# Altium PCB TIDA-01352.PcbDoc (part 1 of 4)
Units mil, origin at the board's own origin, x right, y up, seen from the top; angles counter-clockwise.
Board outline 6496.06 x 8661.42 mil, 4 copper layers (Top Layer, GND, PWR, Bottom Layer), stack 79.834 mil thick; 456 components, 240 nets, 1197 pads, 446 vias.
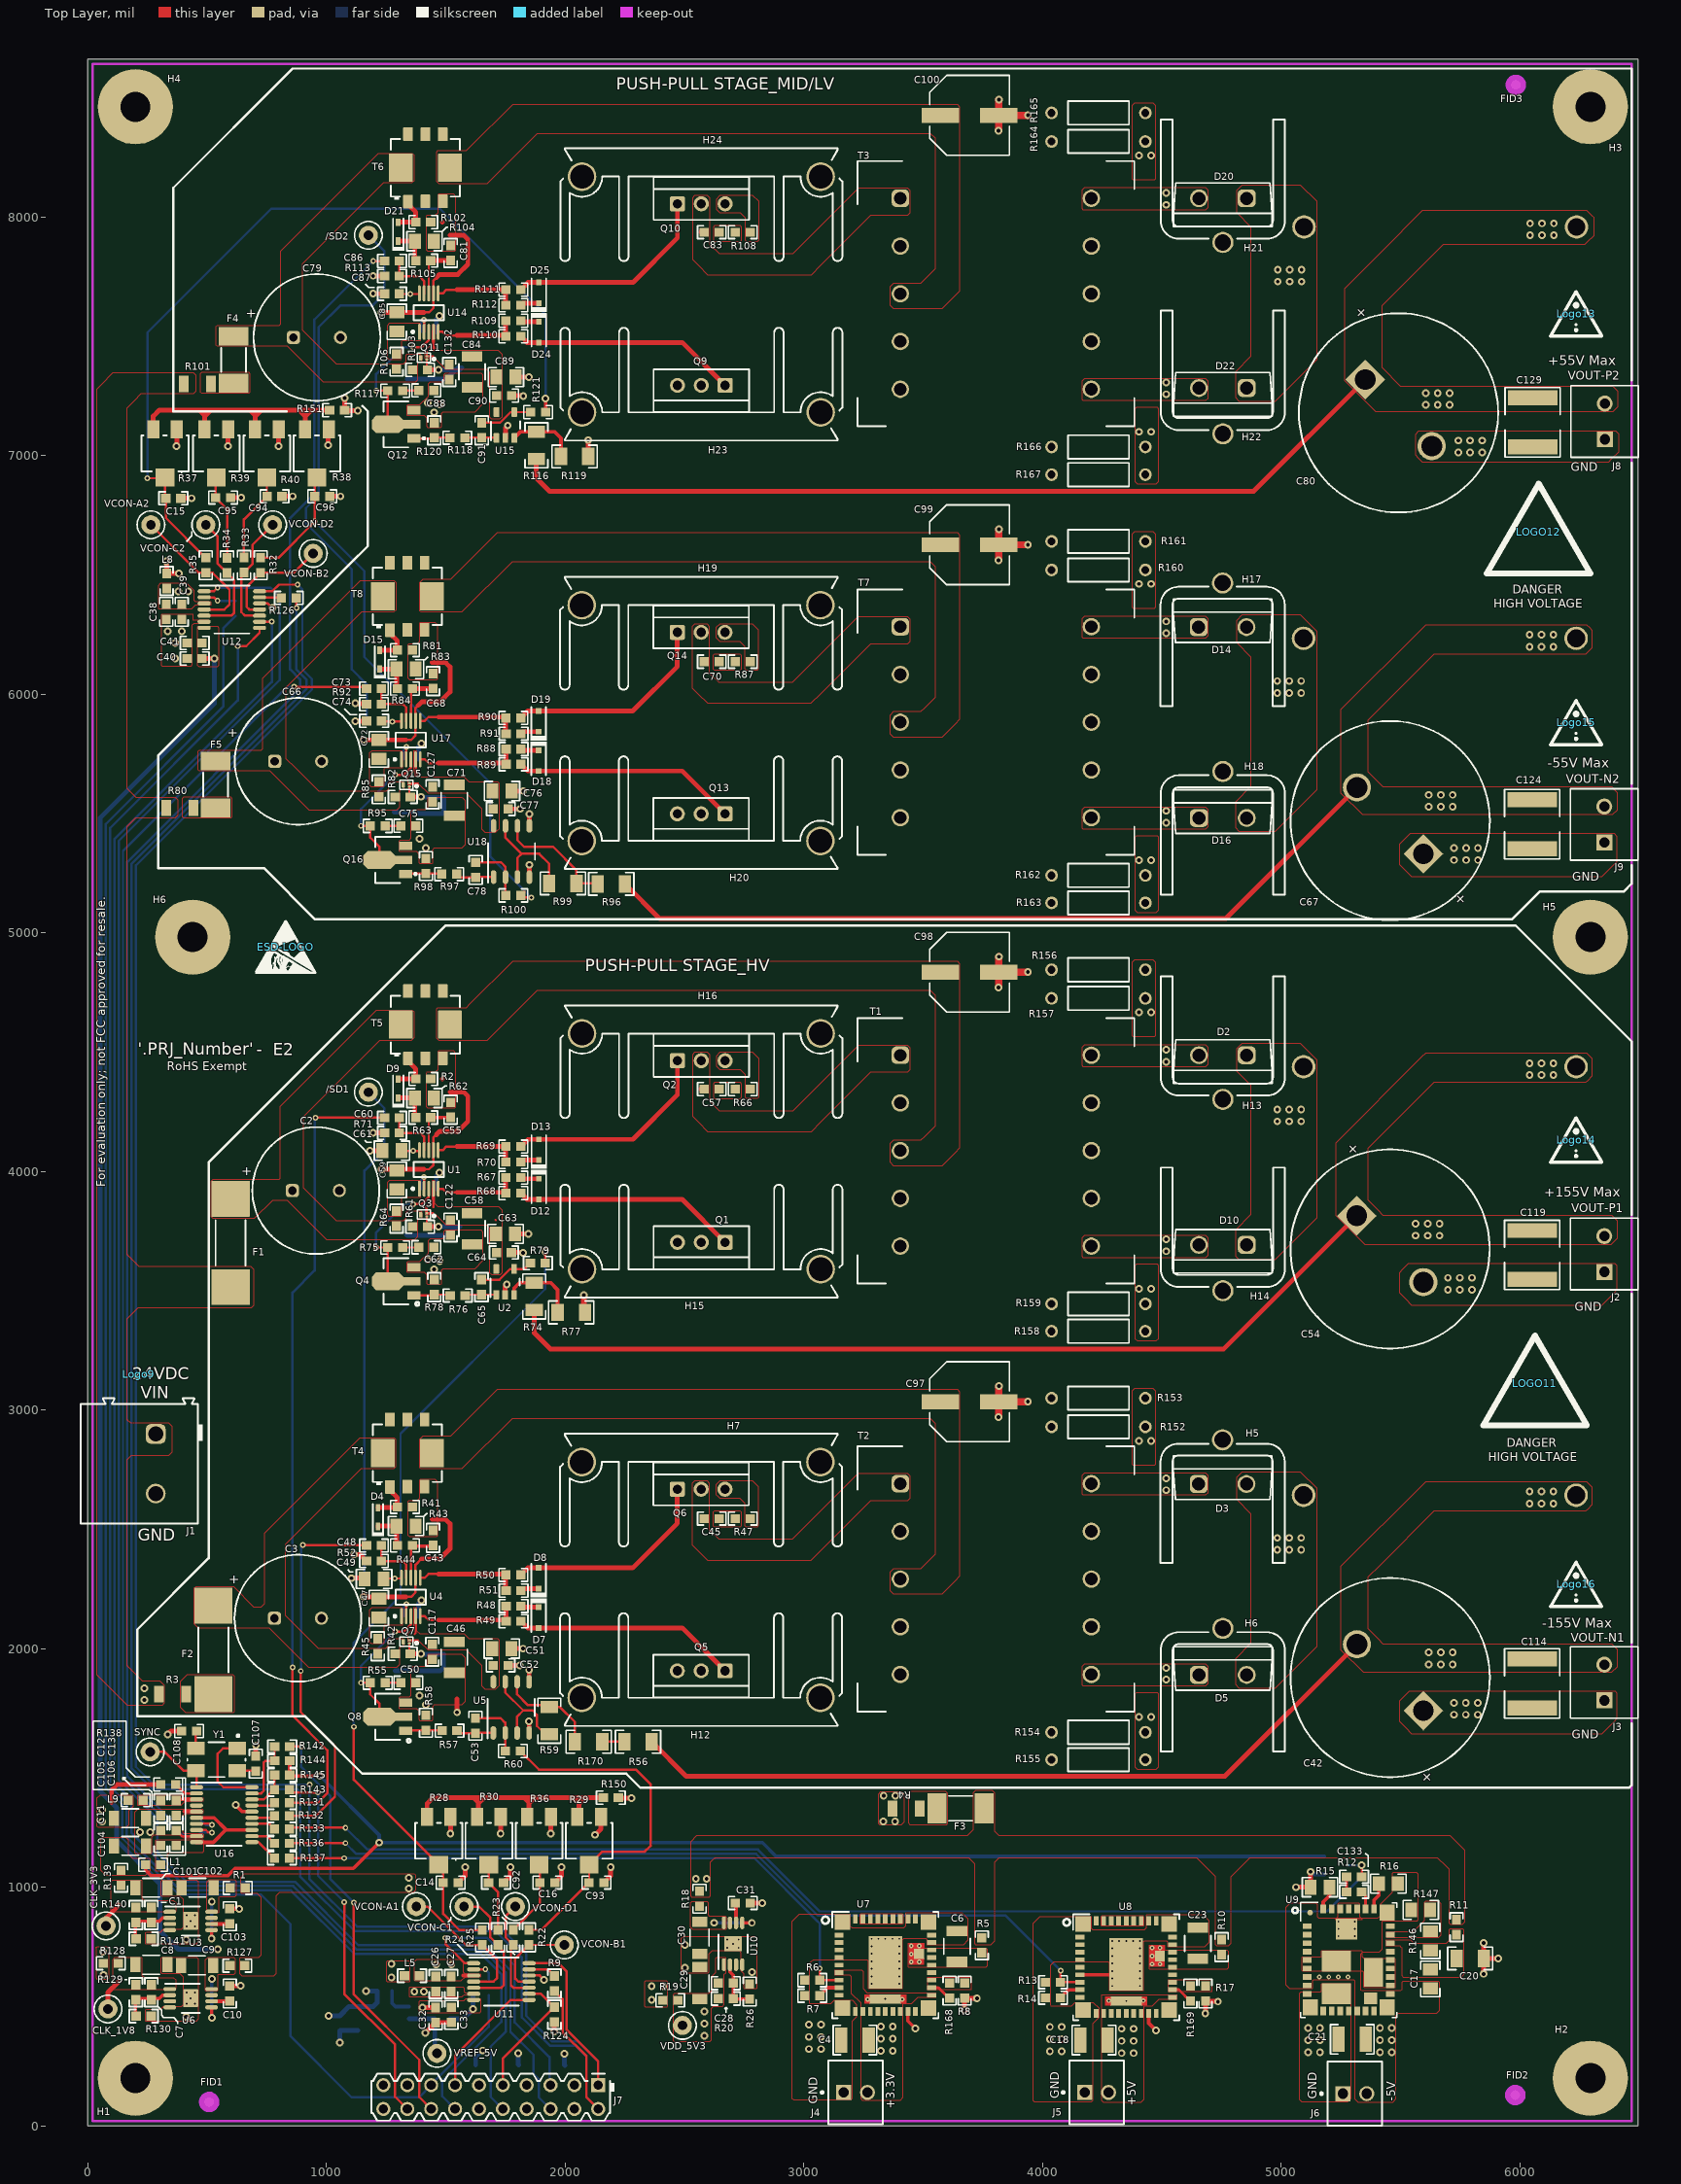
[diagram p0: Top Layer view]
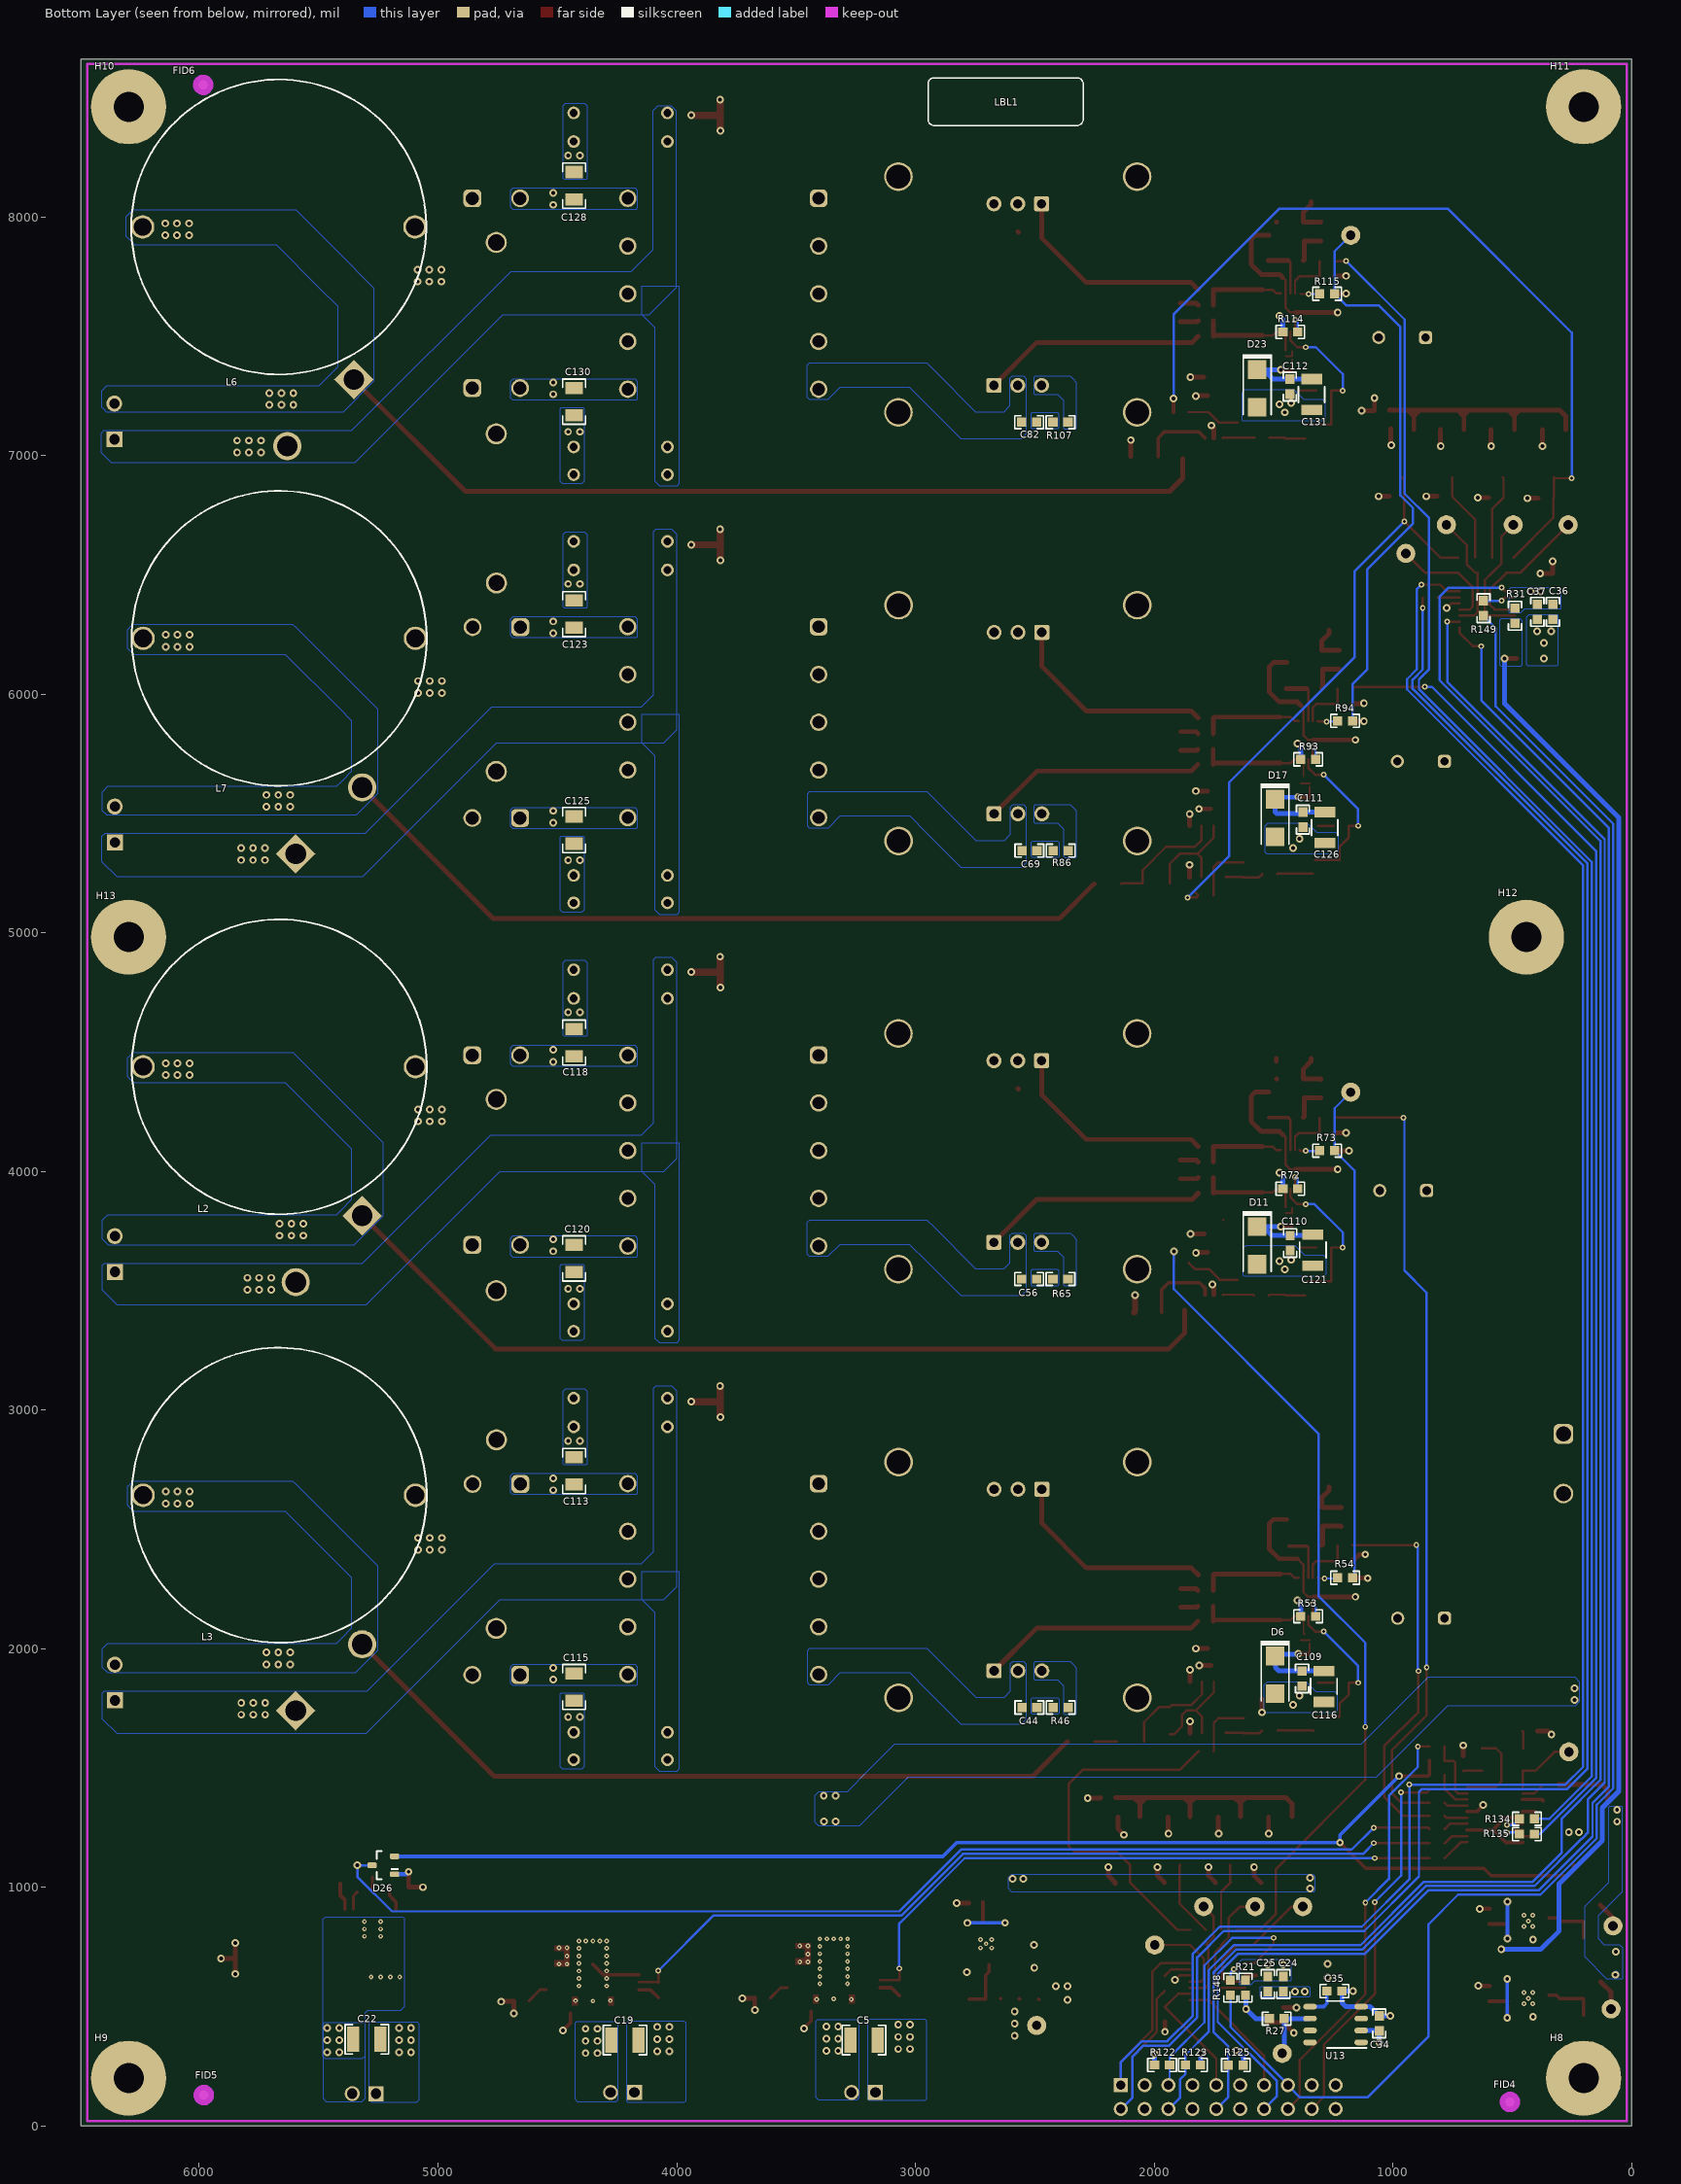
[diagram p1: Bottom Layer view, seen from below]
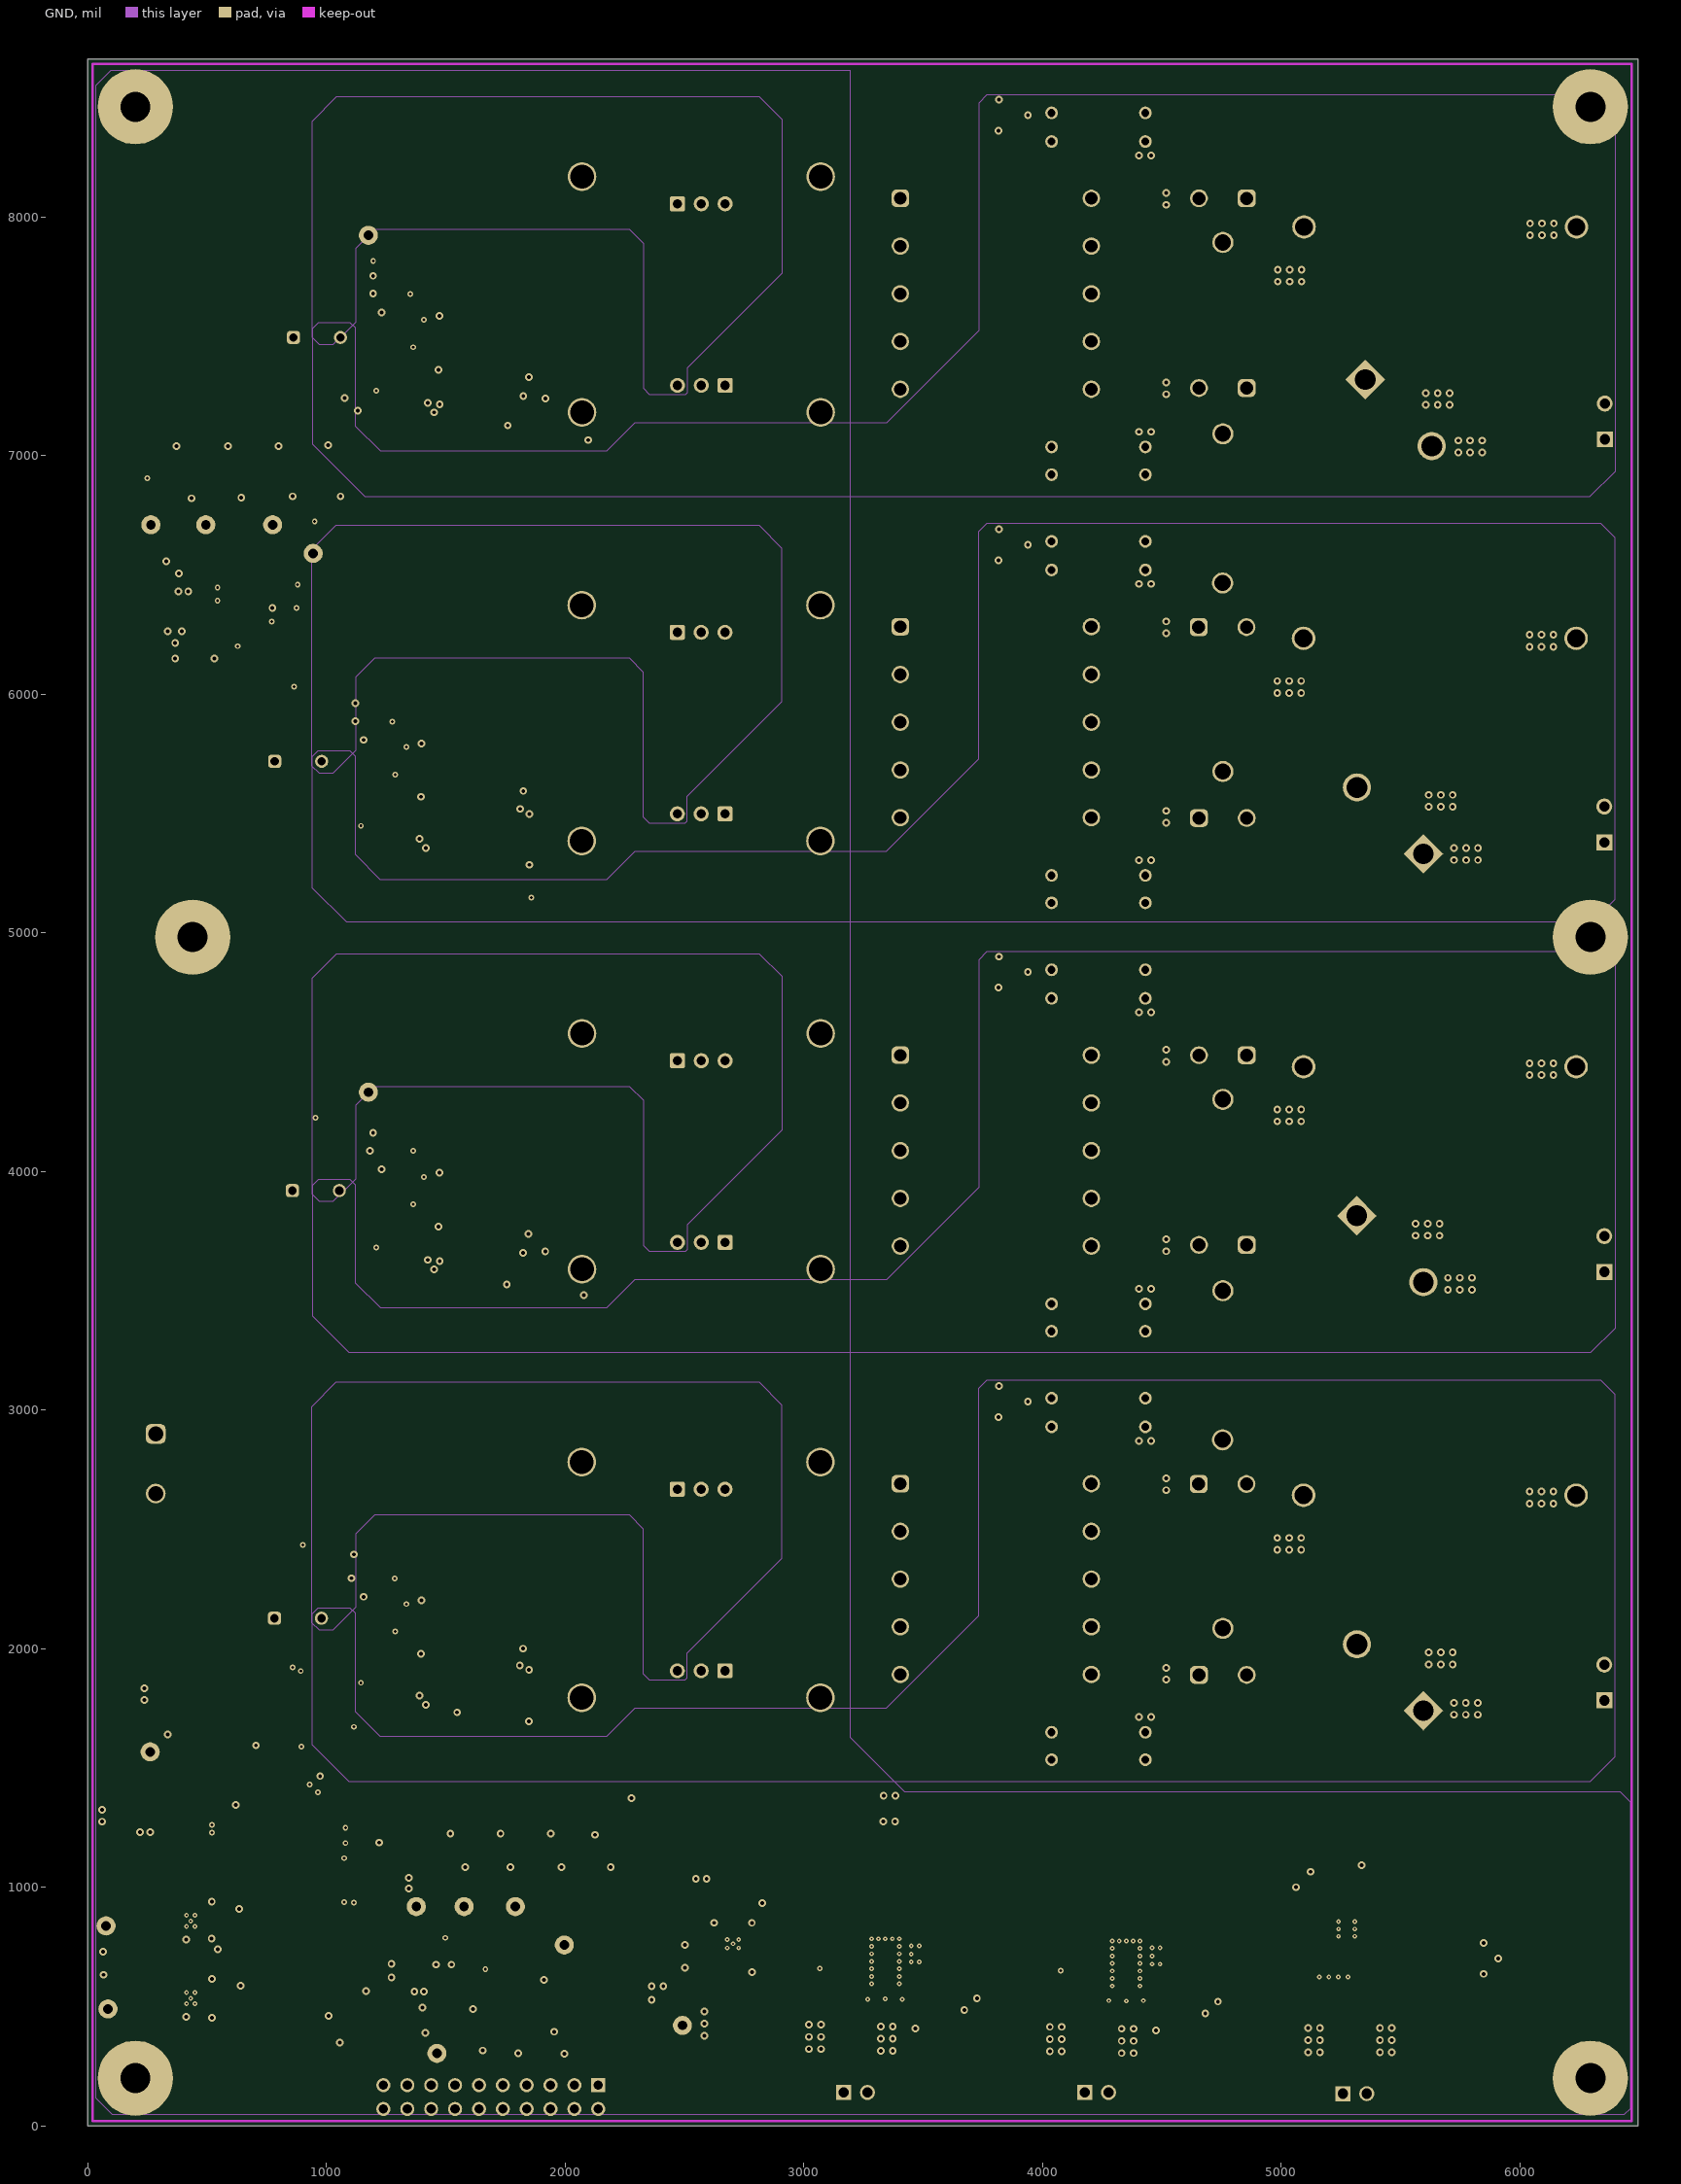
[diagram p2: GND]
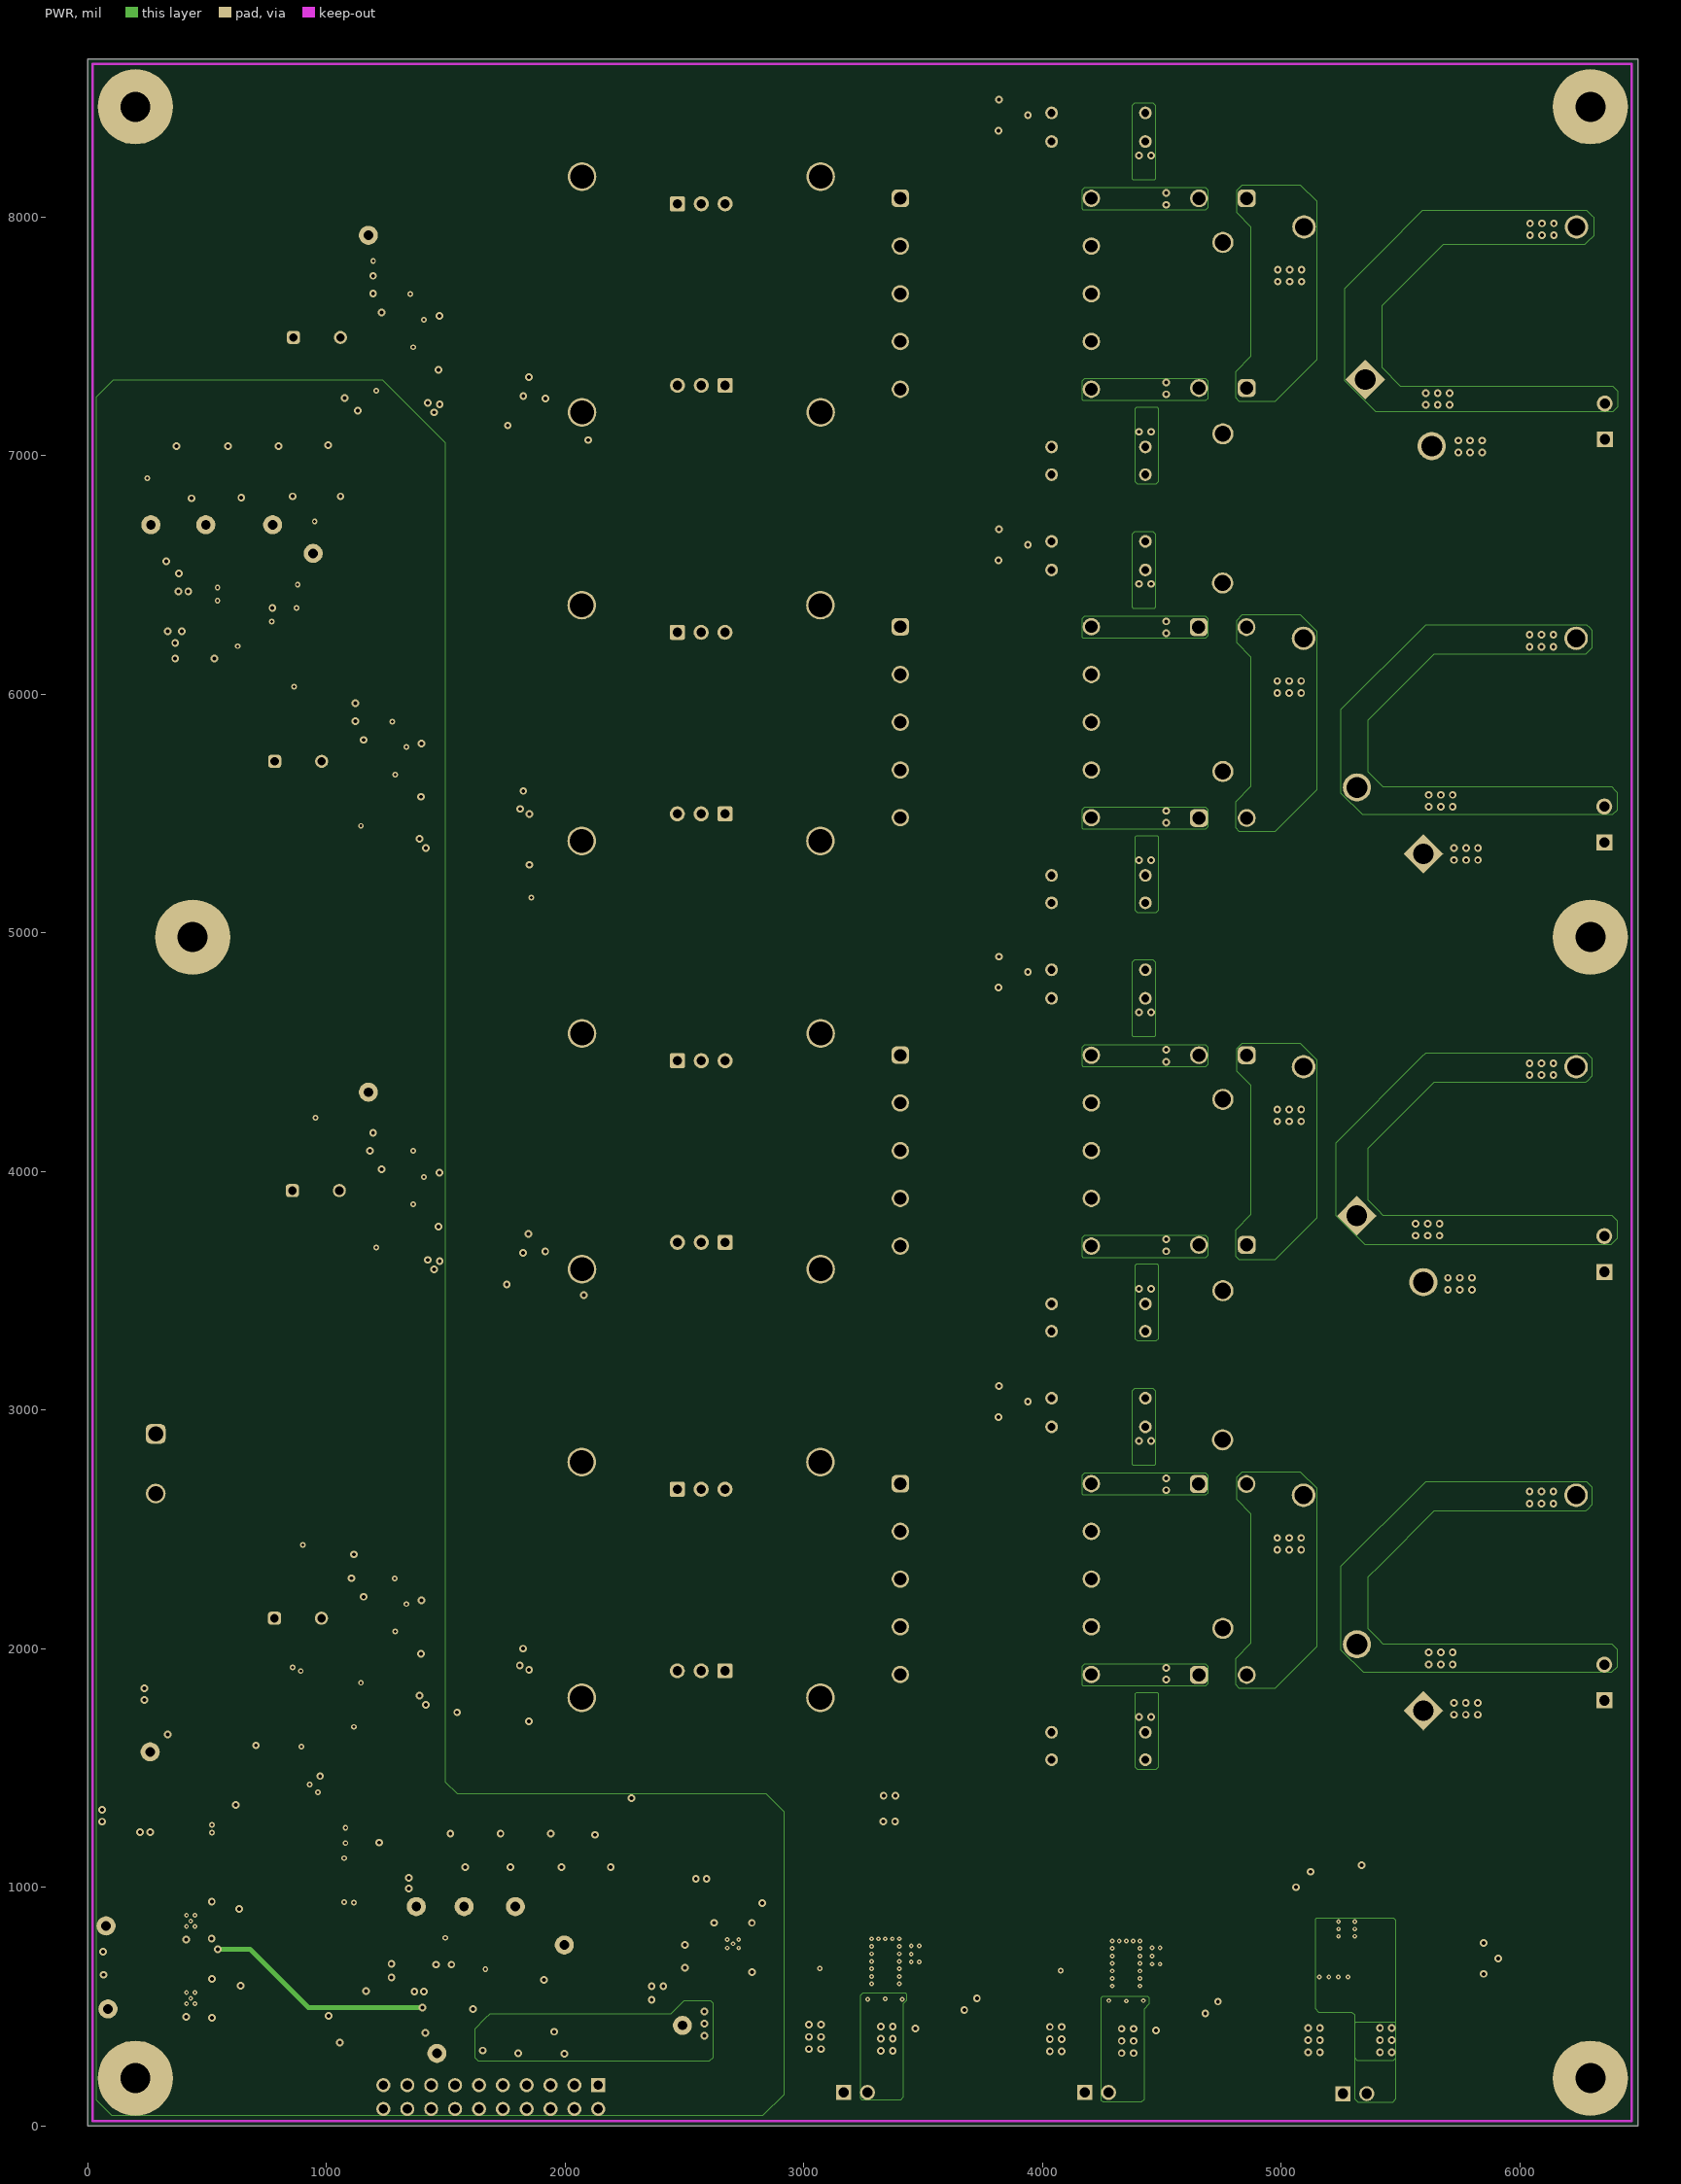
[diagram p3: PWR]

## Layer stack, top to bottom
Top Solder: solder mask 0.4, Solder Resist, Dk 3.5
Top Layer: signal copper 1.4
Dielectric1: core 59.2, FR-4, Dk 4.8
GND: signal copper 1.417
Dielectric 3: prepreg 5, Dk 4.2
PWR: signal copper 1.417
Dielectric 2: core 10, Dk 4.2
Bottom Layer: signal copper 1.4
Bottom Solder: solder mask 0.4, Solder Resist, Dk 3.5

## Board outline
0,0 6496.06,0 6496.06,8661.42 0,8661.42

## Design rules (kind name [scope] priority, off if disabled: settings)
AcuteAngle [All] p0: scope1count=1 scope1_0_kind=Board scope1_0_value=Board scope2count=1 scope2_0_kind=Board scope2_0_value=Board commentlength=0 minimum=4.50000000000000E+0001
AcuteAngle [All] p1: minimum=4.50000000000000E+0001 checktracksonly=FALSE
AssemblyTestPointUsage [All] p0: scope1count=1 scope1_0_kind=Board scope1_0_value=Board scope2count=1 scope2_0_kind=Board scope2_0_value=Board commentlength=0
AssemblyTestPointUsage [All] p1: valid=2
AssemblyTestpoint [All] p0: scope1count=1 scope1_0_kind=Board scope1_0_value=Board scope2count=1 scope2_0_kind=Board scope2_0_value=Board commentlength=0
Clearance "Poly_ All" [All] p0 off: scope1count=1 scope1_0_kind=Board scope1_0_value=Board scope2count=1 scope2_0_kind=Board scope2_0_value=Board commentlength=48 gap=12 // Protel DXP Scope 1 Expression Was: InPolygon
Clearance "SMT Pin Via" [All] p0 off: scope1count=1 scope1_0_kind=Board scope1_0_value=Board scope2count=1 scope2_0_kind=Board scope2_0_value=Board commentlength=47 gap=8 // Protel DXP Scope 2 Expression Was: IsSMTPin
Clearance "Via to Via" [All] p0 off: scope1count=1 scope1_0_kind=Board scope1_0_value=Board scope2count=1 scope2_0_kind=Board scope2_0_value=Board commentlength=44 gap=8 // Protel DXP Scope 2 Expression Was: IsVia
Clearance [All] p0: scope1count=1 scope1_0_kind=Board scope1_0_value=Board scope2count=1 scope2_0_kind=Board scope2_0_value=Board commentlength=0 gap=8
Clearance Poly_Poly [All] p0 off: scope1count=1 scope1_0_kind=Board scope1_0_value=Board scope2count=1 scope2_0_kind=Board scope2_0_value=Board commentlength=48 gap=15 // Protel DXP Scope 2 Expression Was: InPolygon
Clearance "SMT Pin Via" [IsVia vs IsSMTPin] p1: gap=8 ignorepadtopadclearanceinfootprint=FALSE except(0: Arc-Hole Track-Hole SMDPad-Hole THPad-Hole Via-Hole Fill-Hole Poly-Hole Region-Hole Text-Hole)
Clearance "Via to Via" [IsVia vs IsVia] p2: gap=8 ignorepadtopadclearanceinfootprint=FALSE except(0: Arc-Hole Track-Hole SMDPad-Hole THPad-Hole Via-Hole Fill-Hole Poly-Hole Region-Hole Text-Hole)
Clearance Poly_Poly [InPolygon vs InPolygon] p3: gap=15 ignorepadtopadclearanceinfootprint=FALSE except(0: Arc-Hole Track-Hole SMDPad-Hole THPad-Hole Via-Hole Fill-Hole Poly-Hole Region-Hole Text-Hole)
Clearance "Poly_ All" [InPolygon] p4: gap=12 ignorepadtopadclearanceinfootprint=FALSE except(0: Arc-Hole Track-Hole SMDPad-Hole THPad-Hole Via-Hole Fill-Hole Poly-Hole Region-Hole Text-Hole)
Clearance [All] p5: gap=8 ignorepadtopadclearanceinfootprint=FALSE except(0: Arc-Hole Track-Hole SMDPad-Hole THPad-Hole Via-Hole Fill-Hole Poly-Hole Region-Hole Text-Hole; 7.5: SMDPad-SMDPad)
ComponentClearance [All] p0: scope1count=1 scope1_0_kind=Board scope1_0_value=Board scope2count=1 scope2_0_kind=Board scope2_0_value=Board commentlength=0 gap=40 collisioncheckmode=3
ComponentClearance ComponentClearance_THtoTH [All] p0 off: scope1count=1 scope1_0_kind=Board scope1_0_value=Board scope2count=1 scope2_0_kind=Board scope2_0_value=Board commentlength=54 gap=118.11 collisioncheckmode=3 // Protel DXP Scope 2 Expression Was: IsThruComponent
ComponentClearance ComponentClearance_THtoSMT [All] p0 off: scope1count=1 scope1_0_kind=Board scope1_0_value=Board scope2count=1 scope2_0_kind=Board scope2_0_value=Board commentlength=53 gap=100 collisioncheckmode=3 // Protel DXP Scope 2 Expression Was: IsSMTComponent
ComponentClearance ComponentClearance_SmallPassives [All] p0 off: scope1count=1 scope1_0_kind=Board scope1_0_value=Board scope2count=1 scope2_0_kind=Board scope2_0_value=Board commentlength=508 gap=20 collisioncheckmode=3 // Protel DXP Scope 2 Expression Was: HasFootprint('0201*') or HasFootprint('0402*') or HasFootprint('0508') or HasFootprint('0603*') or HasFootprint('0612') or HasFootprint('0805*') or HasFootprint('0815*') or HasFootprint('0830*') or HasFootprint('1206*') or HasFootprint('1210*') or HasFootprint('1808*') or HasFootprint('1812*') or HasFootprint('1825*') or HasFootprint('2010*') or HasFootprint('2220*') or HasFootprint('2225*') or HasFootprint('2512*') or HasFootprint('2728*') or HasFootprint('3518*')
ComponentClearance ComponentClearance_MountingHoles [All] p0: scope1count=1 scope1_0_kind=ComponentClass scope1_0_value="Mounting Holes" scope2count=1 scope2_0_kind=Board scope2_0_value=Board commentlength=0 gap=250 collisioncheckmode=3
ComponentClearance ComponentClearance_ScrewToNut [All] p0 off: scope1count=1 scope1_0_kind=Board scope1_0_value=Board scope2count=1 scope2_0_kind=Board scope2_0_value=Board commentlength=71 gap=5 collisioncheckmode=3 // Protel DXP Scope 2 Expression Was: (HasFootprint('Keystone_1902C'))
ComponentClearance ComponentClearance_Logo [All] p0: scope1count=1 scope1_0_kind=ComponentClass scope1_0_value=Logo scope2count=1 scope2_0_kind=Board scope2_0_value=Board commentlength=0 gap=50 collisioncheckmode=3
ComponentClearance ComponentClearance_Shunt [All] p0: scope1count=1 scope1_0_kind=ComponentClass scope1_0_value=Header scope2count=1 scope2_0_kind=ComponentClass scope2_0_value=Shunt commentlength=0 gap=0 collisioncheckmode=3
ComponentClearance ComponentClearance_Shunt [InComponentClass('Header') vs InComponentClass('Shunt')] p1: gap=0 collisioncheckmode=3 verticalgap=0 showdistances=FALSE
ComponentClearance ComponentClearance_Logo [InComponentClass('Logo')] p2: gap=50 collisioncheckmode=3 verticalgap=10 showdistances=FALSE
ComponentClearance ComponentClearance_ScrewToNut [(HasFootprint('NY PMS 440 0025 PH')) vs (HasFootprint('Keystone_1902C'))] p3: gap=5 collisioncheckmode=3 verticalgap=10 showdistances=FALSE
ComponentClearance ComponentClearance_MountingHoles [InComponentClass('Mounting Holes')] p4: gap=250 collisioncheckmode=3 verticalgap=100000 showdistances=FALSE
ComponentClearance ComponentClearance_SmallPassives [HasFootprint('0201*') or HasFootprint('0402*') or HasFootprint('0508') or HasFootprint('0603*') or HasFootprint('0612') or HasFootprint('0805*') or HasFootprint('0815*') or HasFootprint('0830*') or HasFootprint('1206*') or HasFootprint('1210*') or HasFootprint('1808*') or HasFootprint('1812*') or HasFootprint('1825*') or HasFootprint('2010*') or HasFootprint('2220*') or HasFootprint('2225*') or HasFootprint('2512*') or HasFootprint('2728*') or HasFootprint('3518*') vs HasFootprint('0201*') or HasFootprint('0402*') or HasFootprint('0508') or HasFootprint('0603*') or HasFootprint('0612') or HasFootprint('0805*') or HasFootprint('0815*') or HasFootprint('0830*') or HasFootprint('1206*') or HasFootprint('1210*') or HasFootprint('1808*') or HasFootprint('1812*') or HasFootprint('1825*') or HasFootprint('2010*') or HasFootprint('2220*') or HasFootprint('2225*') or HasFootprint('2512*') or HasFootprint('2728*') or HasFootprint('3518*')] p5: gap=20 collisioncheckmode=3 verticalgap=10 showdistances=FALSE
ComponentClearance ComponentClearance_THtoSMT [IsThruComponent vs IsSMTComponent] p6: gap=100 collisioncheckmode=3 verticalgap=30 showdistances=FALSE
ComponentClearance ComponentClearance_THtoTH [IsThruComponent vs IsThruComponent] p7: gap=118.11 collisioncheckmode=3 verticalgap=30 showdistances=FALSE
ComponentClearance [All] p8: gap=40 collisioncheckmode=3 verticalgap=10 showdistances=FALSE
DiffPairsRouting [All] p0: scope1count=1 scope1_0_kind=Board scope1_0_value=Board scope2count=1 scope2_0_kind=Board scope2_0_value=Board commentlength=0
DiffPairsRouting [All] p1: maxlimit=100 minlimit=10 mostfreqgap=10 toplayer_minwidth=15 toplayer_maxwidth=15 toplayer_prefwidth=15 midlayer1_minwidth=15 midlayer1_maxwidth=15 midlayer1_prefwidth=15 midlayer2_minwidth=15 midlayer2_maxwidth=15 midlayer2_prefwidth=15 bottomlayer_minwidth=15 bottomlayer_maxwidth=15 bottomlayer_prefwidth=15 maxuncoupledlength=1000
FabricationTestPointUsage TestPointUsage [All] p0: scope1count=1 scope1_0_kind=Board scope1_0_value=Board scope2count=1 scope2_0_kind=Board scope2_0_value=Board commentlength=0 valid=2 allowmultiple=FALSE
FabricationTestPointUsage TestPointUsage [All] p1: valid=2 allowmultiple=FALSE
FabricationTestpoint Testpoint [All] p0: scope1count=1 scope1_0_kind=Board scope1_0_value=Board scope2count=1 scope2_0_kind=Board scope2_0_value=Board commentlength=0 side=3 testpointundercomponent=TRUE minsize=40 maxsize=100 preferedsize=60 minholesize=0 maxholesize=40 preferedholesize=32 testpointgrid=1
FabricationTestpoint Testpoint [All] p1: side=3 testpointundercomponent=TRUE minsize=40 maxsize=100 preferedsize=60 minholesize=0 maxholesize=40 preferedholesize=32 testpointgrid=1 allowsidetop=TRUE allowsidebottom=TRUE usegrid=TRUE gridtolerance=0.01
FanoutControl Fanout_Small [All] p0 off: scope1count=1 scope1_0_kind=Board scope1_0_value=Board scope2count=1 scope2_0_kind=Board scope2_0_value=Board commentlength=84 // Protel DXP Scope 1 Expression Was: (CompPinCount < 5)   Fanout_Small (Default Rule)
FanoutControl Fanout_Default [All] p0: scope1count=1 scope1_0_kind=Board scope1_0_value=Board scope2count=1 scope2_0_kind=Board scope2_0_value=Board commentlength=30 // Fanout_Default (Default Rule)
FanoutControl Fanout_SOIC [All] p0 off: scope1count=1 scope1_0_kind=Board scope1_0_value=Board scope2count=1 scope2_0_kind=Board scope2_0_value=Board commentlength=71 // Protel DXP Scope 1 Expression Was: IsSOIC   Fanout_SOIC (Default Rule)
FanoutControl Fanout_BGA [All] p0 off: scope1count=1 scope1_0_kind=Board scope1_0_value=Board scope2count=1 scope2_0_kind=Board scope2_0_value=Board commentlength=69 // Protel DXP Scope 1 Expression Was: IsBGA   Fanout_BGA (Default Rule)
FanoutControl Fanout_LCC [All] p0 off: scope1count=1 scope1_0_kind=Board scope1_0_value=Board scope2count=1 scope2_0_kind=Board scope2_0_value=Board commentlength=69 // Protel DXP Scope 1 Expression Was: IsLCC   Fanout_LCC (Default Rule)
FanoutControl Fanout_LCC [IsLCC] p1: bgadir=Out bgaviamode=Centered fanoutstyle=Auto fanoutdirection=Alternating viagrid=1 // Fanout_LCC (Default Rule)
FanoutControl Fanout_BGA [IsBGA] p2: bgadir=Out bgaviamode=Centered fanoutstyle=Auto fanoutdirection=Alternating viagrid=1 // Fanout_BGA (Default Rule)
FanoutControl Fanout_Default [All] p4: bgadir=Out bgaviamode=Centered fanoutstyle=Auto fanoutdirection=Alternating viagrid=1 // Fanout_Default (Default Rule)
FanoutControl Fanout_Small [(CompPinCount < 5)] p5: bgadir=Out bgaviamode=Centered fanoutstyle=Auto fanoutdirection=OutThenIn viagrid=1 // Fanout_Small (Default Rule)
Height [All] p0: scope1count=1 scope1_0_kind=Board scope1_0_value=Board scope2count=1 scope2_0_kind=Board scope2_0_value=Board commentlength=0
HoleSize [All] p0: scope1count=1 scope1_0_kind=Board scope1_0_value=Board scope2count=1 scope2_0_kind=Board scope2_0_value=Board commentlength=0 absolutevalues=TRUE maxlimit=251 minlimit=7.87 maxpercent=80.000 minpercent=20.000
HoleSize [All] p1: absolutevalues=TRUE maxlimit=251 minlimit=7.87 maxpercent=80.000 minpercent=20.000
HoleToHoleClearance [All] p0: scope1count=1 scope1_0_kind=Board scope1_0_value=Board scope2count=1 scope2_0_kind=Board scope2_0_value=Board commentlength=0
LayerPairs [All] p0: scope1count=1 scope1_0_kind=Board scope1_0_value=Board scope2count=1 scope2_0_kind=Board scope2_0_value=Board commentlength=0 enforce=TRUE
MinimumAnnularRing [All] p0: scope1count=1 scope1_0_kind=Board scope1_0_value=Board scope2count=1 scope2_0_kind=Board scope2_0_value=Board commentlength=0 minimumring=5.91
MinimumAnnularRing MinimumAnnularRing_ThermalPadVias [All] p0 off: scope1count=1 scope1_0_kind=Board scope1_0_value=Board scope2count=1 scope2_0_kind=Board scope2_0_value=Board commentlength=63 minimumring=5.91 // Protel DXP Scope 1 Expression Was: IsVia and InAnyComponent
MinimumAnnularRing MinimumAnnularRing_ThermalPadVias [IsVia and InAnyComponent] p1: minimumring=5.91
MinimumAnnularRing [All] p2: minimumring=5.91
MinimumSolderMaskSliver [All] p0: scope1count=1 scope1_0_kind=Board scope1_0_value=Board scope2count=1 scope2_0_kind=Board scope2_0_value=Board commentlength=0
MinimumSolderMaskSliver MinimumSolderMaskSliver_Logo [All] p0: scope1count=1 scope1_0_kind=ComponentClass scope1_0_value=Logo scope2count=1 scope2_0_kind=ComponentClass scope2_0_value=Logo commentlength=0
MinimumSolderMaskSliver MinimumSolderMaskSliver_Logo [InComponentClass('Logo') vs InComponentClass('Logo')] p1: minsoldermaskwidth=0.7
MinimumSolderMaskSliver [All] p2: minsoldermaskwidth=3.94
NetAntennae [All] p0: scope1count=1 scope1_0_kind=Board scope1_0_value=Board scope2count=1 scope2_0_kind=Board scope2_0_value=Board commentlength=0
PasteMaskExpansion [All] p0: scope1count=1 scope1_0_kind=Board scope1_0_value=Board scope2count=1 scope2_0_kind=Board scope2_0_value=Board commentlength=0 expansion=0
PlaneClearance [All] p0: scope1count=1 scope1_0_kind=Board scope1_0_value=Board scope2count=1 scope2_0_kind=Board scope2_0_value=Board commentlength=0 clearance=20
PlaneConnect [All] p0: scope1count=1 scope1_0_kind=Board scope1_0_value=Board scope2count=1 scope2_0_kind=Board scope2_0_value=Board commentlength=0 planeconnectstyle=Direct reliefexpansion=10 reliefentries=4 reliefconductorwidth=10 reliefairgap=10
PlaneConnect [All] p1: planeconnectstyle=Direct reliefexpansion=10 reliefentries=4 reliefconductorwidth=10 reliefairgap=10
PolygonConnect [All] p0: scope1count=1 scope1_0_kind=Board scope1_0_value=Board scope2count=1 scope2_0_kind=Board scope2_0_value=Board commentlength=0 connectstyle=Direct reliefconductorwidth=10 reliefentries=4 polygonreliefangle="90 Angle"
PolygonConnect [All] p1: connectstyle=Direct reliefconductorwidth=10 reliefentries=4 polygonreliefangle="90 Angle" airgapwidth=10
RoutingCorners [All] p0: scope1count=1 scope1_0_kind=Board scope1_0_value=Board scope2count=1 scope2_0_kind=Board scope2_0_value=Board commentlength=0 cornerstyle=45-Degree minsetback=100 maxsetback=100
RoutingLayers [All] p0: scope1count=1 scope1_0_kind=Board scope1_0_value=Board scope2count=1 scope2_0_kind=Board scope2_0_value=Board commentlength=0 top layer=Automatic mid layer 1=Automatic mid layer 2=Automatic bottom layer=Automatic
RoutingPriority [All] p0: scope1count=1 scope1_0_kind=Board scope1_0_value=Board scope2count=1 scope2_0_kind=Board scope2_0_value=Board commentlength=0
RoutingTopology [All] p0: scope1count=1 scope1_0_kind=Board scope1_0_value=Board scope2count=1 scope2_0_kind=Board scope2_0_value=Board commentlength=0 topology=Shortest
RoutingVias RoutingVias_power [All] p0: scope1count=1 scope1_0_kind=NetClass scope1_0_value=power scope2count=1 scope2_0_kind=Board scope2_0_value=Board commentlength=0 holewidth=16 width=30 viastyle="Through Hole" minholewidth=7.87 minwidth=19.68 maxholewidth=16 maxwidth=30
RoutingVias [All] p0: scope1count=1 scope1_0_kind=Board scope1_0_value=Board scope2count=1 scope2_0_kind=Board scope2_0_value=Board commentlength=0 holewidth=12 width=24 viastyle="Through Hole" minholewidth=7.87 minwidth=19.68 maxholewidth=16 maxwidth=32
RoutingVias RoutingVias_power [InNetClass('power')] p1: holewidth=16 width=30 viastyle="Through Hole" minholewidth=7.87 minwidth=19.68 maxholewidth=16 maxwidth=30
RoutingVias [All] p2: holewidth=12 width=24 viastyle="Through Hole" minholewidth=7.87 minwidth=19.68 maxholewidth=16 maxwidth=32
SMDToCorner [All] p0: scope1count=1 scope1_0_kind=Board scope1_0_value=Board scope2count=1 scope2_0_kind=Board scope2_0_value=Board commentlength=0 distance=30000
SMDToCorner [All] p1: distance=30000
ShortCircuit [All] p0: scope1count=1 scope1_0_kind=Board scope1_0_value=Board scope2count=1 scope2_0_kind=Board scope2_0_value=Board commentlength=0 allowed=FALSE
SilkToBoardRegionClearance [All] p0: scope1count=1 scope1_0_kind=Board scope1_0_value=Board scope2count=1 scope2_0_kind=Board scope2_0_value=Board commentlength=0
SilkToSilkClearance [All] p0: scope1count=1 scope1_0_kind=Board scope1_0_value=Board scope2count=1 scope2_0_kind=Board scope2_0_value=Board commentlength=0
SilkToSilkClearance [All] p1: silktosilkclearance=5
SilkToSolderMaskClearance SilkscreenOverComponentPads [All] p0 off: scope1count=1 scope1_0_kind=Board scope1_0_value=Board scope2count=1 scope2_0_kind=Board scope2_0_value=Board commentlength=44 // Protel DXP Scope 1 Expression Was: IsPad
SilkToSolderMaskClearance SilkscreenOverComponentPads [IsPad] p1: minsilkscreentomaskgap=5 clearancetoexposedcopper=TRUE
SolderMaskExpansion [All] p0: scope1count=1 scope1_0_kind=Board scope1_0_value=Board scope2count=1 scope2_0_kind=Board scope2_0_value=Board commentlength=0 expansion=2.5
SolderMaskExpansion [All] p1: expansion=2.5 istentingtop=FALSE
UnRoutedNet [All] p0: scope1count=1 scope1_0_kind=Board scope1_0_value=Board scope2count=1 scope2_0_kind=Board scope2_0_value=Board commentlength=0
UnpouredPolygon [All] p0: scope1count=1 scope1_0_kind=Board scope1_0_value=Board scope2count=1 scope2_0_kind=Board scope2_0_value=Board commentlength=0
Width Width_power [All] p0: scope1count=1 scope1_0_kind=NetClass scope1_0_value=power scope2count=1 scope2_0_kind=Board scope2_0_value=Board commentlength=0 maxlimit=200 minlimit=10 preferedwidth=20
Width [All] p0: scope1count=1 scope1_0_kind=Board scope1_0_value=Board scope2count=1 scope2_0_kind=Board scope2_0_value=Board commentlength=0 maxlimit=200 minlimit=8 preferedwidth=20
Width Width_power [InNetClass('power')] p1: maxlimit=200 minlimit=10 preferedwidth=20
Width [All] p2: maxlimit=200 minlimit=8 preferedwidth=20 checkconnectedcopper=TRUE
16 further rules are at their usual default settings.

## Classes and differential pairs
component class "Mounting Holes": H1 H2 H3 H4 H5 H6
component class FiducialMark: FID1 FID2 FID3 FID4 FID5 FID6
component class Header: J7
component class TIDA-01352_Hardware: 4 ESD-LOGO FID1 FID2 FID3 FID4 FID5 FID6 H1 H2 H3 H4 H5 H6 H8 H9 H10 H11 H12 H13 LBL1 Logo9 Logo10 LOGO11 LOGO12 Logo13 Logo14 Logo15 Logo16 ZZ8 ZZ9 ZZ10 ZZ11
component class AssemblyNote: ZZ8 ZZ9 ZZ10 ZZ11
component class Label: LBL1
component class TIDA-01352_Aux_Supply_Generation: C4 C5 C6 C17 C18 C19 C20 C21 C22 C23 C133 D26 F3 J4 J5 J6 R4 R5 R6 R7 R8 R10 R11 R12 R13 R14 R15 R16 R17 R146 R147 R168 R169 U7 U8 U9
component class TIDA-01352_DAC_and_Control: C14 C15 C16 C24 C25 C26 C27 C28 C29 C30 C31 C32 C33 C34 C35 C36 C37 C38 C39 C40 C41 C92 C93 C94 C95 C96 J7 L5 L8 R9 R18 R19 R20 R21 R22 R23 R24 R25 R26 R27 R28 R29 R30 R31 R32 R33 R34 R35 R36 R37 R38 R39 R40 R122 R123 R124 R125 R126 R148 R149 R150 R151 U10 U11 U12 U13 VCON-A1 VCON-A2 VCON-B1 VCON-B2 VCON-C1 VCON-C2 VCON-D1 VCON-D2 VDD_5V3 VREF_5V
component class "TIDA-01352_Push-Pull Stage_Negative-MID": C66 C67 C68 C69 C70 C71 C72 C73 C74 C75 C76 C77 C78 C99 C111 C123 C124 C125 C126 C127 D14 D15 D16 D17 D18 D19 F5 H17 H18 H19 H20 J9 L7 Q13 Q14 Q15 Q16 R80 R81 R82 R83 R84 R85 R86 R87 R88 R89 R90 R91 R92 R93 R94 R95 R96 R97 R98 R99 R100 R160 R161 R162 R163 T7 T8 U17 U18
component class "TIDA-01352_Push-Pull Stage_Negative_MAIN": C3 C42 C43 C44 C45 C46 C47 C48 C49 C50 C51 C52 C53 C97 C109 C113 C114 C115 C116 C117 D3 D4 D5 D6 D7 D8 F2 H5 H6 H7 H12 J3 L3 Q5 Q6 Q7 Q8 R3 R41 R42 R43 R44 R45 R46 R47 R48 R49 R50 R51 R52 R53 R54 R55 R56 R57 R58 R59 R60 R152 R153 R154 R155 R170 T2 T4 U4 U5
component class "TIDA-01352_Push-Pull Stage_Positive-MID": /SD2 C79 C80 C81 C82 C83 C84 C85 C86 C87 C88 C89 C90 C91 C100 C112 C128 C129 C130 C131 C132 D20 D21 D22 D23 D24 D25 F4 H21 H22 H23 H24 J8 L6 Q9 Q10 Q11 Q12 R101 R102 R103 R104 R105 R106 R107 R108 R109 R110 R111 R112 R113 R114 R115 R116 R117 R118 R119 R120 R121 R164 R165 R166 R167 T3 T6 U14 U15
component class "TIDA-01352_Push-Pull Stage_Positive_MAIN": /SD1 C2 C54 C55 C56 C57 C58 C59 C60 C61 C62 C63 C64 C65 C98 C110 C118 C119 C120 C121 C122 D2 D9 D10 D11 D12 D13 F1 H13 H14 H15 H16 J1 J2 L2 Q1 Q2 Q3 Q4 R2 R61 R62 R63 R64 R65 R66 R67 R68 R69 R70 R71 R72 R73 R74 R75 R76 R77 R78 R79 R156 R157 R158 R159 T1 T5 U1 U2
component class TIDA-01352-Clock-Sync: C1 C7 C8 C9 C10 C11 C12 C13 C101 C102 C103 C104 C105 C106 C107 C108 CLK_1V8 CLK_3V3 L1 L9 R1 R127 R128 R129 R130 R131 R132 R133 R134 R135 R136 R137 R138 R139 R140 R141 R142 R143 R144 R145 SYNC U3 U6 U16 Y1

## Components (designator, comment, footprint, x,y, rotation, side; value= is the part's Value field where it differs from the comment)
/SD1 "5002" Keystone5002 1176,4332 r90 top
/SD2 "5002" Keystone5002 1176,7923.01 r90 top
C1 "GRM188R71H103KA01D" 0603#1 266.83,883.87 r90 top
C2 "860080778023" WCAP-ATLI_1300x3000 956,3919.56 r0 top locked
C3 "860080778023" WCAP-ATLI_1300x3000 881,2127.43 r0 top locked
C4 "GRM32ER61C476KE15L" 1210_270 3215.11,360 r180 top
C5 "GRM32ER61C476KE15L" 1210_270 3215.11,360 r180 bottom
C6 "C3225X5R1H106K250AB" 1210_280 3642.11,752 r90 top
C7 "GRM188R71H103KA01D" 0603#1 266.83,560 r90 top
C8 "C3216X5R1H106K160AB" 1206_180 266.83,675 r0 top
C9 "C3216X5R1H106K160AB" 1206_180 458.23,672.61 r180 top
C10 "GRM188R71H103KA01D" 0603#1 595.37,554.69 r270 top
C11 "C3216X5R1H106K160AB" 1206_180 177.89,1289.5 r0 top
C12 "C1608X5R1E105K080AC" 0603#1 305.89,1331.86 r270 top
C13 "C0603C104K5RACTU" 0603#1 370.89,1331.86 r270 top
C14 "06033C104JAT2A" 0603#1 1521,1019.63 r0 top
C15 "06033C104JAT2A" 0603#1 358.9,6820.8 r0 top
C16 "06033C104JAT2A" 0603#1 1925.5,1019.63 r0 top
C17 "C2012X5R1H225K125AB" 0805_HV 5625.11,616 r90 top
C18 "GRM32ER61C476KE15L" 1210_270 4216.11,360 r180 top
C19 "GRM32ER61C476KE15L" 1210_270 4216.11,360 r180 bottom
C20 "C3216X5R1H475K085AB" 1206 5792,702 r0 top
C21 "GRM32ER61C476KE15L" 1210_270 5298.11,363 r180 top
C22 "GRM32ER61C476KE15L" 1210_270 5298.11,363 r180 bottom
C23 "C3225X5R1H106K250AB" 1210_280 4651.11,765.04 r90 top
C24 "GRM188R61E106MA73D" 0603#1 1458.33,594.63 r270 bottom
C25 "C1608X5R1E105K080AC" 0603#1 1523.33,594.63 r270 bottom
C26 "C0603C104K5RACTU" 0603#1 1458.33,594.63 r270 top
C27 "GRM1885C1H101JA01D" 0603#1 1523.33,594.63 r270 top
C28 "GRM188R71H103KA01D" 0603#1 2673.8,598.22 r180 top
C29 "C3216X5R1H106K160AB" 1206_180 2563.8,598.22 r90 top
C30 "C3216X5R1H106K160AB" 1206_180 2563.8,788.22 r270 top
C31 "GRM188R71H103KA01D" 0603#1 2744.8,934.02 r180 top
C32 "GRM188R61E106MA73D" 0603#1 1457.6,464.01 r270 top
C33 "C1608X5R1E105K080AC" 0603#1 1523.6,465.01 r270 top
C34 "C1608X5R1E105K080AC" 0603#1 1056.26,429.63 r90 bottom
C35 "C1608X5R1E105K080AC" 0603#1 1244.37,564.63 r180 bottom
C36 "GRM188R61E106MA73D" 0603#1 329.1,6344.71 r270 bottom
C37 "C1608X5R1E105K080AC" 0603#1 394.1,6344.71 r270 bottom
C38 "C0603C104K5RACTU" 0603#1 329.1,6344.71 r270 top
C39 "GRM1885C1H101JA01D" 0603#1 394.1,6344.71 r270 top
C40 "GRM188R61E106MA73D" 0603#1 448.1,6149.71 r180 top
C41 "C1608X5R1E105K080AC" 0603#1 448.1,6214.71 r180 top
C42 "LLS2G101MELY" Nichicon_2000x3000_Snap 5457,1879 r135 top
C43 "GRM188R71E102KA01D" 0603#1 1447,2464 r90 top
C44 "GRM188R71E102KA01D" 0603#1 2522.15,1753.11 r180 bottom
C45 "GRM188R71E102KA01D" 0603#1 2615,2545 r0 top
C46 "12103D226MAT2A" 1210_280 1536,1964 r270 top
C47 "08055C105KAT2A" 0805_HV 1220,2170 r90 top
C48 "06035A101FAT2A" 0603#1 1199.57,2432.13 r180 top
C49 "C2012X5R1V156M125AC" 0805_HV 1200,2292 r180 top
C50 "GMK107BJ105KA-T" 0603#1 1343.93,1857 r0 top
C51 "08055C105KAT2A" 0805_HV 1735,2000 r0 top
C52 "06035C104KAT2A" 0603#1 1730,1930 r0 top
C53 "06035C104KAT2A" 0603#1 1624.46,1677.15 r270 top
C54 "LLS2G101MELY" Nichicon_2000x3000_Snap 5456.7,3675 r315 top
C55 "GRM188R71E102KA01D" 0603#1 1521,4258.14 r90 top
C56 "GRM188R71E102KA01D" 0603#1 2523,3549 r180 bottom
C57 "GRM188R71E102KA01D" 0603#1 2615,4345 r0 top
C58 "12103D226MAT2A" 1210_280 1610,3759.96 r270 top
C59 "08055C105KAT2A" 0805_HV 1295,3964 r90 top
C60 "06035A101FAT2A" 0603#1 1275,4224.27 r180 top
C61 "C2012X5R1V156M125AC" 0805_HV 1275,4087 r180 top
C62 "GMK107BJ105KA-T" 0603#1 1418.93,3681.94 r0 top
C63 "08055C105KAT2A" 0805_HV 1751,3738 r0 top
C64 "06035C104KAT2A" 0603#1 1744,3660 r0 top
C65 "06035C104KAT2A" 0603#1 1650,3515 r270 top
C66 "860080778023" WCAP-ATLI_1300x3000 882.1,5718.43 r0 top locked
C67 "LLS2G101MELY" Nichicon_2000x3000_Snap 5457,5470 r135 top
C68 "GRM188R71E102KA01D" 0603#1 1447,6055.01 r90 top
C69 "GRM188R71E102KA01D" 0603#1 2522.15,5344.12 r180 bottom
C70 "GRM188R71E102KA01D" 0603#1 2615,6136.01 r0 top
C71 "12103D226MAT2A" 1210_280 1536,5555.01 r270 top
C72 "08055C105KAT2A" 0805_HV 1220.13,5768.43 r90 top
C73 "06035A101FAT2A" 0603#1 1199.57,6023.13 r180 top
C74 "C1608X5R1E685K080AC" 0603#1 1200,5888.01 r180 top
C75 "GMK107BJ105KA-T" 0603#1 1343.93,5448.01 r0 top
C76 "08055C105KAT2A" 0805_HV 1736.1,5594.2 r0 top
C77 "06035C104KAT2A" 0603#1 1731.1,5519.2 r0 top
C78 "06035C104KAT2A" 0603#1 1625.56,5263.85 r270 top
C79 "860080778023" WCAP-ATLI_1300x3000 960.56,7494.9 r0 top locked
C80 "LLS2G101MELY" Nichicon_2000x3000_Snap 5492,7179 r315 top
C81 "GRM188R71E102KA01D" 0603#1 1521,7849.15 r90 top
C82 "GRM188R71E102KA01D" 0603#1 2523,7140.01 r180 bottom
C83 "GRM188R71E102KA01D" 0603#1 2615,7936.01 r0 top
C84 "12103D226MAT2A" 1210_280 1610,7350.97 r270 top
C85 "08055C105KAT2A" 0805_HV 1295.13,7560.01 r90 top
C86 "06035A101FAT2A" 0603#1 1275,7815.27 r180 top
C87 "C1608X5R1E685K080AC" 0603#1 1275,7678.01 r180 top
C88 "GMK107BJ105KA-T" 0603#1 1418.93,7272.95 r0 top
C89 "08055C105KAT2A" 0805_HV 1752.12,7328.94 r0 top
C90 "06035C104KAT2A" 0603#1 1745.12,7250.94 r0 top
C91 "06035C104KAT2A" 0603#1 1651.12,7105.94 r270 top
C92 "06033C104JAT2A" 0603#1 1711.26,1019.63 r0 top
C93 "06033C104JAT2A" 0603#1 2131.26,1019.63 r0 top
C94 "06033C104JAT2A" 0603#1 782.82,6828.9 r0 top
C95 "06033C104JAT2A" 0603#1 567.2,6823.9 r0 top
C96 "06033C104JAT2A" 0603#1 982.82,6828.9 r0 top
C97 "EEE-FC1H220P" SM_RADIAL_E 3695,3035 r0 top
C98 "EEE-FC1H220P" SM_RADIAL_E 3695,4835 r0 top
C99 "EEE-FC1H220P" SM_RADIAL_E 3695,6626.01 r0 top
C100 "EEE-FC1H220P" SM_RADIAL_E 3695,8426.01 r0 top
C101 "C3216X5R1H106K160AB" 1206_180 266.93,997.9 r0 top
C102 "C3216X5R1H106K160AB" 1206_180 460.37,997.9 r180 top
C103 "GRM188R71H103KA01D" 0603#1 595.37,878.57 r270 top
C104 "C3216X5R1H106K160AB" 1206_180 177.89,1173.5 r0 top
C105 "C1608X5R1E105K080AC" 0603#1 305.89,1206.86 r90 top
C106 "C0603C104K5RACTU" 0603#1 370.89,1206.86 r90 top
C107 "C0603C100F5GAC7867" 0603#1 704.5,1518.11 r270 top
C108 "C0603C100F5GAC7867" 0603#1 424.89,1654.5 r0 top
C109 "06035C104KAT2A" 0603#1 1380,1875 r270 bottom
C110 "06035C104KAT2A" 0603#1 1430,3700 r270 bottom
C111 "06035C104KAT2A" 0603#1 1376.1,5474.2 r270 bottom
C112 "06035C104KAT2A" 0603#1 1431.1,7289.2 r270 bottom
C113 "VJ1206Y471KBEAT4X" 1206 4430,2744.5 r270 bottom
C114 "GRM55DR72E105KW01L" 2220_200 6052,1854 r270 top
C115 "VJ1206Y471KBEAT4X" 1206 4430,1839.5 r270 bottom
C116 "12103D226MAT2A" 1210_280 1288.46,1841.54 r270 bottom
C117 "06035C104KAT2A" 0603#1 1444,1987 r270 top
C118 "VJ1206Y471KBEAT4X" 1206 4430,4540 r270 bottom
C119 "GRM55DR72E105KW01L" 2220_200 6052,3650 r270 top
C120 "VJ1206Y471KBEAT4X" 1206 4430,3635 r270 bottom
C121 "12103D226MAT2A" 1210_280 1335,3670 r270 bottom
C122 "06035C104KAT2A" 0603#1 1520,3765 r270 top
C123 "VJ1206Y471KBEAT4X" 1206 4430,6335.5 r270 bottom
C124 "GRM55DR72E105KW01L" 2220_200 6052,5455 r270 top
C125 "VJ1206Y471KBEAT4X" 1206 4430,5430.5 r270 bottom
C126 "12103D226MAT2A" 1210_280 1284.57,5440.74 r270 bottom
C127 "06035C104KAT2A" 0603#1 1445,5580 r270 top
C128 "VJ1206Y471KBEAT4X" 1206 4430,8131.01 r270 bottom
C129 "GRM55DR72E105KW01L" 2220_200 6054,7139 r270 top
C130 "VJ1206Y471KBEAT4X" 1206 4430,7226.01 r270 bottom
C131 "12103D226MAT2A" 1210_280 1339.57,7255.74 r270 bottom
C132 "06035C104KAT2A" 0603#1 1515,7350 r270 top
C133 "06035A471JAT2A" 0603#1 5306,1044 r0 top
CLK_1V8 "5002" Keystone5002 85,490.02 r90 top
CLK_3V3 "5002" Keystone5002 77,838 r90 top
D2 "LXA10T600" TO-220AC 4756,4487 r180 top
D3 "LXA10T600" TO-220AC 4755,2690 r0 top
D4 "1N4148WT" Fairchild_SOD-523F 1216.15,2551.25 r90 top
D5 "LXA10T600" TO-220AC 4756,1890 r0 top
D6 "1SMA5926BT3G" SMA 1493,1890 r270 bottom
D7 "PMEG1030EJ,115" SOD-323F 1889.15,2130.11 r270 top
D8 "PMEG1030EJ,115" SOD-323F 1889.15,2295.11 r90 top
D9 "1N4148WT" Fairchild_SOD-523F 1301,4347.14 r90 top
D10 "LXA10T600" TO-220AC 4756,3692 r180 top
D11 "1SMA5926BT3G" SMA 1568,3690.09 r270 bottom
D12 "PMEG1030EJ,115" SOD-323F 1890.13,3926 r270 top
D13 "PMEG1030EJ,115" SOD-323F 1890,4091 r90 top
D14 "LXA10T600" TO-220AC 4755,6281.01 r0 top
D15 "1N4148WT" Fairchild_SOD-523F 1223.85,6144.89 r90 top
D16 "LXA10T600" TO-220AC 4756,5481.01 r0 top
D17 "1SMA5926BT3G" SMA 1493,5481.01 r270 bottom
D18 "PMEG1030EJ,115" SOD-323F 1889.15,5721.12 r270 top
D19 "PMEG1030EJ,115" SOD-323F 1889.15,5886.12 r90 top
D20 "LXA10T600" TO-220AC 4756,8078.01 r180 top
D21 "1N4148WT" Fairchild_SOD-523F 1301,7938.15 r90 top
D22 "LXA10T600" TO-220AC 4756,7283.01 r180 top
D23 "1SMA5926BT3G" SMA 1568,7281.1 r270 bottom
D24 "PMEG1030EJ,115" SOD-323F 1890.13,7517.01 r270 top
D25 "PMEG1030EJ,115" SOD-323F 1890,7682.01 r90 top
D26 "BAV99,215" SOT-23 5229,1092 r0 bottom
ESD-LOGO "ESD Susceptible" ESD_Overlay_medium 830,4940 r0 top
F1 "0678L9150-02" Fuse_0678L 599,3700 r270 top
F2 "0678L9150-02" Fuse_0678L 527,1995 r270 top
F3 "0679L9100-01" Fuse_SSQ 3657.11,1330.28 r180 top
F4 "0679L9100-01" Fuse_SSQ 611.1,7401.2 r270 top
F5 "0679L9100-01" Fuse_SSQ 536.1,5621.2 r270 top
FID1 "Fiducial" Fiducial10-20 509.11,100 r90 top
FID2 "Fiducial" Fiducial10-20 5981,129 r90 top
FID3 "Fiducial" Fiducial10-20 5983.59,8553.53 r90 top
FID4 "Fiducial" Fiducial10-20 509.11,100 r90 bottom
FID5 "Fiducial" Fiducial10-20 5981,129 r90 bottom
FID6 "Fiducial" Fiducial10-20 5983.59,8553.53 r90 bottom
H1 "NY PMS 440 0025 PH" "NY PMS 440 0025 PH" 200,200 r0 top
H2 "NY PMS 440 0025 PH" "NY PMS 440 0025 PH" 6296.06,200 r0 top
H3 "NY PMS 440 0025 PH" "NY PMS 440 0025 PH" 6296.06,8461.42 r0 top
H4 "NY PMS 440 0025 PH" "NY PMS 440 0025 PH" 200,8461.42 r0 top
H5 "NY PMS 440 0025 PH" "NY PMS 440 0025 PH" 6296.06,4982 r0 top
H5 "577202B04000G" Aavid_577202B04000G 4755,2875 r180 top
H6 "NY PMS 440 0025 PH" "NY PMS 440 0025 PH" 440,4982 r0 top
H6 "577202B04000G" Aavid_577202B04000G 4756,2085 r180 top
H7 "V6560X" ASMN_V6560X 2570.15,2782.11 r180 top locked
H8 "1902E" Keystone_1902E 200,200 r180 bottom
H9 "1902E" Keystone_1902E 6296.06,200 r180 bottom
H10 "1902E" Keystone_1902E 6296.06,8461.42 r180 bottom
H11 "1902E" Keystone_1902E 200,8461.42 r180 bottom
H12 "1902E" Keystone_1902E 440,4982 r180 bottom
H12 "V6560X" ASMN_V6560X 2570.15,1794.11 r0 top locked
H13 "1902E" Keystone_1902E 6296.06,4982 r180 bottom
H13 "577202B04000G" Aavid_577202B04000G 4756,4302 r0 top
H14 "577202B04000G" Aavid_577202B04000G 4756,3500 r0 top
H15 "V6560X" ASMN_V6560X 2571,3590 r0 top locked
H16 "V6560X" ASMN_V6560X 2571,4578 r180 top locked
H17 "577202B04000G" Aavid_577202B04000G 4755,6466.01 r180 top
H18 "577202B04000G" Aavid_577202B04000G 4756,5676.01 r180 top
H19 "V6560X" ASMN_V6560X 2570.15,6373.12 r180 top locked
H20 "V6560X" ASMN_V6560X 2570.15,5385.12 r0 top locked
H21 "577202B04000G" Aavid_577202B04000G 4756,7893.01 r0 top
H22 "577202B04000G" Aavid_577202B04000G 4756,7091.01 r0 top
H23 "V6560X" ASMN_V6560X 2571,7181.01 r0 top locked
H24 "V6560X" ASMN_V6560X 2571,8169.01 r180 top locked
J1 "OSTT7020150" On-Shore_OSTT7020150 285,2775 r270 top
J2 "1727010" PhoenixConact_1727010 6354,3654 r90 top
J3 "1727010" PhoenixConact_1727010 6354,1858 r90 top
J4 "282834-2" TEC_282834-2 3217.11,140 r0 top
J5 "282834-2" TEC_282834-2 4227.11,140 r0 top
J6 "282834-2" TEC_282834-2 5309.11,135 r0 top
J7 "PRPC010DAAN-RC" Sullins_xxxC010DAAN 1689.26,120.63 r270 top
J8 "1727010" PhoenixConact_1727010 6356,7143 r90 top
J9 "1727010" PhoenixConact_1727010 6354,5454 r90 top
L1 "BLM18EG601SH1" 0603#1 273.89,1094.5 r0 top
L2 "1447440C" 1447440C 5665,4438.5 r0 bottom
L3 "1447440C" 1447440C 5665,2643 r0 bottom
L5 "BLM18BB050SN1D" 0603#1 1359,629 r0 top
L6 "1447440C" 1447440C 5667,7958 r0 bottom
L7 "1447440C" 1447440C 5665,6234.01 r0 bottom
L8 "BLM18BB050SN1D" 0603#1 330.76,6474.3 r270 top
L9 "BLM18EG601SH1" 0603#1 200.89,1364.5 r0 top
LBL1 "Size: 0.65\" x 0.20 \"" Label_650x200 2622,8483 r0 bottom
Logo9 "EU RoHS Exempt Logo" EURoHS_Exempt_60mil 215,3150 r0 top
Logo10 "FCC disclaimer" FCC_disclaimer -290,3930 r90 bottom
LOGO11 "DANGER HIGH VOLTAGE" IEC_HighVoltage_medium 6064,3111 r0 top
LOGO12 "DANGER HIGH VOLTAGE" IEC_HighVoltage_medium 6079,6681 r0 top
Logo13 "CAUTION.  READ USER GUIDE BEFORE USE" IEC_Caution_small 6236,7594 r0 top
Logo14 "CAUTION.  READ USER GUIDE BEFORE USE" IEC_Caution_small 6236,4132 r0 top
Logo15 "CAUTION.  READ USER GUIDE BEFORE USE" IEC_Caution_small 6236,5881 r0 top
Logo16 "CAUTION.  READ USER GUIDE BEFORE USE" IEC_Caution_small 6236,2270 r0 top
Q1 "CSD19506KCS" KCS0003B 2571,3703 r270 top locked
Q2 "CSD19506KCS" KCS0003B 2571,4464 r90 top
Q3 "CSD17381F4" YJC0003A 1408,3818.27 r180 top
Q4 "FCX493TA" SOT-89-3 1292.2,3539.94 r180 top
Q5 "CSD19506KCS" KCS0003B 2570.15,1907.11 r270 top locked
Q6 "CSD19506KCS" KCS0003B 2570.15,2668.11 r90 top
Q7 "CSD17381F4" YJC0003A 1335.13,2028.43 r180 top
Q8 "FCX493TA" SOT-89-3 1257.46,1714.15 r180 top
Q9 "CSD19506KCS" KCS0003B 2571,7294.01 r270 top locked
Q10 "CSD19506KCS" KCS0003B 2571,8055.01 r90 top
Q11 "CSD17381F4" YJC0003A 1408,7409.27 r180 top
Q12 "FCX493TA" SOT-89-3 1292.2,7130.95 r180 top
Q13 "CSD19506KCS" KCS0003B 2570.15,5498.12 r270 top locked
Q14 "CSD19506KCS" KCS0003B 2570.15,6259.12 r90 top
Q15 "CSD17381F4" YJC0003A 1335.13,5619.43 r180 top
Q16 "FCX493TA" SOT-89-3 1257.46,5305.16 r180 top
R1 "CRCW06030000Z0EA" 0603#1 629,997.5 r0 top
R2 "CRCW060310K0FKEA" 0603#1 1406,4387.14 r180 top
R3 "5108" 5108 356,1809 r0 top
R4 "5108" 5108 3429.11,1330 r0 top
R5 "CRCW06030000Z0EA" 0603#1 3746.11,757 r90 top
R6 "CRCW06030000Z0EA" 0603#1 3035.61,610.73 r0 top
R7 "CRCW0603200KFKEA" 0603#1 3035.61,545.73 r0 top
R8 "CRCW06038K87FKEA" 0603#1 3674.11,566.72 r90 top
R9 "CRCW06030000Z0EA" 0603#1 1955.36,596.63 r270 top
R10 "CRCW06030000Z0EA" 0603#1 4751.11,749 r90 top
R11 "CRCW06030000Z0EA" 0603#1 5735,833 r90 top
R12 "CRCW06031K00FKEA" 0603#1 5306,981 r180 top
R13 "CRCW06030000Z0EA" 0603#1 4044.61,602 r0 top
R14 "CRCW0603200KFKEA" 0603#1 4044.61,537 r0 top
R15 "CRCW080552K3FKEA" 0805_HV 5163.11,1000 r0 top
R16 "CRCW080593K1FKEA" 0805_HV 5449.57,1015 r0 top
R17 "CRCW06035K11FKEA" 0603#1 4683,554.5 r90 top
R18 "CRCW06030000Z0EA" 0603#1 2563.8,952.02 r90 top
R19 "CRCW06030000Z0EA" 0603#1 2440.8,526.02 r0 top
R20 "CRCW0603348KFKEA" 0603#1 2673.8,533.22 r0 top
R21 "CRCW06030000Z0EA" 0603#1 1617.19,579.04 r270 bottom
R22 "CRCW06030000Z0EA" 0603#1 1849,790 r270 top
R23 "CRCW06030000Z0EA" 0603#1 1783,790 r270 top
R24 "CRCW06030000Z0EA" 0603#1 1719,790 r270 top
R25 "CRCW06030000Z0EA" 0603#1 1653.33,789.63 r270 top
R26 "RC0603FR-07100KL" 0603#1 2773.8,563.22 r90 top
R27 "CRCW06030000Z0EA" 0603#1 1486.14,449.63 r180 bottom
R28 "3224X-1-102E" TRIM_3224X 1471.26,1194.63 r270 top
R29 "3224X-1-102E" TRIM_3224X 2101.26,1194.63 r270 top
R30 "3224X-1-102E" TRIM_3224X 1681.26,1194.63 r270 top
R31 "CRCW06030000Z0EA" 0603#1 487.96,6329.12 r270 bottom
R32 "CRCW06030000Z0EA" 0603#1 725,6540 r270 top
R33 "CRCW06030000Z0EA" 0603#1 655,6541.5 r270 top
R34 "CRCW06030000Z0EA" 0603#1 584.1,6539.71 r270 top
R35 "CRCW06030000Z0EA" 0603#1 495,6540 r270 top
R36 "3224X-1-102E" TRIM_3224X 1891.26,1194.63 r270 top
R37 "3224X-1-102E" TRIM_3224X 324.2,7008.9 r270 top
R38 "3224X-1-102E" TRIM_3224X 960.82,7008.9 r270 top
R39 "3224X-1-102E" TRIM_3224X 539.2,7008.9 r270 top
R40 "3224X-1-102E" TRIM_3224X 750.82,7008.9 r270 top
R41 "CRCW060310K0FKEA" 0603#1 1328.85,2593.88 r180 top
R42 "CRCW060310K0FKEA" 0603#1 1320.13,1978.43 r180 top
R43 "CRCW08054R02FKEA" 0805_HV 1333.85,2513.88 r0 top
R44 "RC0603FR-07300RL" 0603#1 1328.85,2432.43 r180 top
R45 "CRCW06030000Z0EA" 0603#1 1215,2010 r270 top
R46 "CRCW06030000Z0EA" 0603#1 2391.15,1753.11 r180 bottom
R47 "CRCW06030000Z0EA" 0603#1 2745,2545 r0 top
R48 "CRCW06030000Z0EA" 0603#1 1784.15,2178.54 r180 top
R49 "CRCW060310R0FKEA" 0603#2 1784.15,2178.54 r0 top
R50 "CRCW060310R0FKEA" 0603#1 1783.15,2309.11 r0 top
R51 "CRCW06030000Z0EA" 0603#1 1784.15,2243.11 r180 top
R52 "CRCW060326K7FKEA" 0603#1 1199.57,2367.13 r0 top
R53 "CRCW06030000Z0EA" 0603#1 1354.13,2135.72 r180 bottom
R54 "CRCW06030000Z0EA" 0603#1 1200,2297 r0 bottom
R55 "CRCW06031K00FKEA" 0603#1 1215,1857 r180 top
R56 "RC1206FR-07300KL" 1206 2306,1610 r0 top
R57 "RC0603FR-0747KL" 0603#1 1516,1656 r0 top
R58 "CRCW060310K0FKEA" 0603#1 1417.46,1689.15 r270 top
R59 "CRCW120610K0FKEA" 1206 1934,1698 r90 top
R60 "RC0603FR-0747KL" 0603#1 1780.95,1571.05 r0 top
R61 "CRCW060310K0FKEA" 0603#1 1393,3768.27 r180 top
R62 "CRCW08054R02FKEA" 0805_HV 1411,4307.14 r0 top
R63 "RC0603FR-07300RL" 0603#1 1406,4225.68 r180 top
R64 "CRCW06030000Z0EA" 0603#1 1294,3802.27 r270 top
R65 "CRCW06030000Z0EA" 0603#1 2392,3549 r180 bottom
R66 "CRCW06030000Z0EA" 0603#1 2745,4345 r0 top
R67 "CRCW06030000Z0EA" 0603#1 1783,3974 r180 top
R68 "CRCW060310R0FKEA" 0603#1 1783,3909 r0 top
R69 "CRCW060310R0FKEA" 0603#1 1783,4104 r0 top
R70 "CRCW06030000Z0EA" 0603#1 1783,4039 r180 top
R71 "CRCW060326K7FKEA" 0603#1 1275,4161.14 r0 top
R72 "CRCW06030000Z0EA" 0603#1 1429.13,3927.29 r180 bottom
R73 "CRCW06030000Z0EA" 0603#1 1275,4087 r0 bottom
R74 "RC1206FR-07300KL" 1206 1871,3476 r270 top
R75 "CRCW06031K00FKEA" 0603#1 1288.93,3680.94 r180 top
R76 "RC0603FR-0747KL" 0603#1 1550,3480 r0 top
R77 "CRCW120610K0FKEA" 1206 2026,3409 r180 top
R78 "CRCW060310K0FKEA" 0603#1 1452.2,3514.94 r270 top
R79 "RC0603FR-0747KL" 0603#1 1886,3616 r0 top
R80 "5108" 5108 386.1,5523.2 r0 top
R81 "CRCW060310K0FKEA" 0603#1 1328.85,6184.89 r180 top
R82 "CRCW060310K0FKEA" 0603#1 1320.13,5569.43 r180 top
R83 "CRCW08054R99FKEA" 0805_HV 1333.85,6104.89 r0 top
R84 "RC0603FR-07300RL" 0603#1 1328.85,6023.43 r180 top
R85 "CRCW06030000Z0EA" 0603#1 1220,5601.01 r270 top
R86 "CRCW06030000Z0EA" 0603#1 2391.15,5344.12 r180 bottom
R87 "CRCW06030000Z0EA" 0603#1 2745,6136.01 r0 top
R88 "CRCW06030000Z0EA" 0603#1 1784.15,5769.54 r180 top
R89 "CRCW060310R0FKEA" 0603#2 1784.15,5769.54 r0 top
R90 "CRCW060310R0FKEA" 0603#1 1783.15,5900.12 r0 top
R91 "CRCW06030000Z0EA" 0603#1 1784.15,5834.12 r180 top
R92 "CRCW060326K7FKEA" 0603#1 1199.57,5958.13 r0 top
R93 "CRCW06030000Z0EA" 0603#1 1354.13,5726.72 r180 bottom
R94 "CRCW06030000Z0EA" 0603#1 1200,5888.01 r0 bottom
R95 "CRCW06031K00FKEA" 0603#1 1215,5448.01 r180 top
R96 "CRCW1206110KFKEA" 1206 2194,5205 r0 top
R97 "RC0603FR-0747KL" 0603#1 1515.06,5245.85 r0 top
R98 "CRCW060310K0FKEA" 0603#1 1417.46,5280.16 r270 top
R99 "CRCW120610K0FKEA" 1206 1991,5207 r180 top
R100 "RC0603FR-0747KL" 0603#1 1783.1,5156.7 r0 top
R101 "5108" 5108 460,7300 r0 top
R102 "CRCW060310K0FKEA" 0603#1 1406,7978.15 r180 top
R103 "CRCW060310K0FKEA" 0603#1 1393,7359.27 r180 top
R104 "CRCW08054R99FKEA" 0805_HV 1411,7898.15 r0 top
R105 "RC0603FR-07300RL" 0603#1 1406,7816.69 r180 top
R106 "CRCW06030000Z0EA" 0603#1 1294,7393.27 r270 top
R107 "CRCW06030000Z0EA" 0603#1 2392,7140.01 r180 bottom
R108 "CRCW06030000Z0EA" 0603#1 2745,7936.01 r0 top
R109 "CRCW06030000Z0EA" 0603#1 1783,7565.01 r180 top
R110 "CRCW060310R0FKEA" 0603#1 1783,7500.01 r0 top
R111 "CRCW060310R0FKEA" 0603#1 1783,7695.01 r0 top
R112 "CRCW06030000Z0EA" 0603#1 1783,7630.01 r180 top
R113 "CRCW060326K7FKEA" 0603#1 1275,7752.15 r0 top
R114 "CRCW06030000Z0EA" 0603#1 1429.13,7518.3 r180 bottom
R115 "CRCW06030000Z0EA" 0603#1 1275,7678.01 r0 bottom
R116 "CRCW1206100KFKEA" 1206 1880,7043 r270 top
R117 "CRCW06031K00FKEA" 0603#1 1288.93,7271.95 r180 top
R118 "RC0603FR-0747KL" 0603#1 1548.69,7074.46 r0 top
R119 "CRCW120610K0FKEA" 1206 2040,6996 r180 top
R120 "CRCW060310K0FKEA" 0603#1 1452.2,7105.95 r270 top
R121 "RC0603FR-0747KL" 0603#1 1887.12,7181.94 r0 top
R122 "CRCW06030000Z0EA" 0603#1 1966.26,255.63 r0 bottom
R123 "CRCW06030000Z0EA" 0603#1 1837.26,255.63 r0 bottom
R124 "CRCW06030000Z0EA" 0603#1 1955.36,466.23 r270 top
R125 "CRCW06030000Z0EA" 0603#1 1657.26,254.63 r0 bottom
R126 "CRCW06030000Z0EA" 0603#1 843.1,6403.2 r0 top
R127 "CRCW06030000Z0EA" 0603#1 627.26,671.53 r0 top
R128 "CRCW06030000Z0EA" 0603#1 97.26,681.53 r0 top
R129 "RT0603DRE0751K7L" 0603#1 201.83,560 r270 top
R130 "RC0603FR-07100KL" 0603#1 234.83,460 r0 top
R131 "CRCW06030000Z0EA" 0603#1 813.89,1353.86 r180 top
R132 "CRCW06030000Z0EA" 0603#1 813.89,1298.86 r180 top
R133 "CRCW06030000Z0EA" 0603#1 813.89,1243.86 r180 top
R134 "CRCW06030000Z0EA" 0603#1 437.5,1287 r0 bottom
R135 "CRCW06030000Z0EA" 0603#1 438,1223 r0 bottom
R136 "CRCW06030000Z0EA" 0603#1 814,1184 r180 top
R137 "CRCW06030000Z0EA" 0603#1 814,1122 r180 top
R138 "CRCW06030000Z0EA" 0603#1 337.89,1430.5 r0 top
R139 "CRCW06030000Z0EA" 0603#1 140,1040 r270 top
R140 "CRCW0603178KFKEA" 0603#1 201.83,883.87 r270 top
R141 "RC0603FR-07100KL" 0603#1 234.83,783.87 r0 top
R142 "CRCW06030000Z0EA" 0603#1 815,1590 r180 top
R143 "CRCW06030000Z0EA" 0603#1 813.89,1408.86 r180 top
R144 "RC0603JR-0710KL" 0603#1 815,1530 r180 top
R145 "RC0603JR-0710KL" 0603#1 815,1470 r180 top
R146 "CRCW0805174KFKEA" 0805_HV 5625,775 r270 top
R147 "CRCW080563K4FKEA" 0805_HV 5585,905 r0 top
R148 "CRCW06030000Z0EA" 0603#1 1680,579 r270 bottom
R149 "CRCW06030000Z0EA" 0603#1 620,6360 r270 bottom
R150 "CRCW06030000Z0EA" 0603#1 2192.05,1375.74 r0 top
R151 "CRCW06030000Z0EA" 0603#1 1045,7190 r0 top
R152 "PR01000101101JR500" PR01 4235,2929.5 r180 top
R153 "PR01000101101JR500" PR01 4235,3049.5 r180 top
R154 "PR01000101101JR500" PR01 4235,1649.5 r0 top
R155 "PR01000101101JR500" PR01 4235,1534.5 r0 top
R156 "PR01000101101JR500" PR01 4235,4845 r180 top
R157 "PR01000101101JR500" PR01 4235,4725 r180 top
R158 "PR01000101101JR500" PR01 4235,3330 r0 top
R159 "PR01000101101JR500" PR01 4235,3445 r0 top
R160 "PR01000101101JR500" PR01 4235,6520.5 r180 top
R161 "PR01000101101JR500" PR01 4235,6640.5 r180 top
R162 "PR01000101101JR500" PR01 4235,5240.5 r0 top
R163 "PR01000101101JR500" PR01 4235,5125.5 r0 top
R164 "PR01000101101JR500" PR01 4235,8316.01 r180 top
R165 "PR01000101101JR500" PR01 4235,8436.01 r180 top
R166 "PR01000101101JR500" PR01 4235,7036.01 r0 top
R167 "PR01000101101JR500" PR01 4235,6920 r0 top
R168 "CRCW06030000Z0EA" 0603#1 3611,567 r270 top
R169 "CRCW06030000Z0EA" 0603#1 4620,555 r270 top
R170 "CRCW120610K0FKEA" 1206 2099,1610 r180 top
SYNC "5002" Keystone5002 261.89,1567.5 r90 top
T1 "750343547" Wurth_750343473 3805,4087 r0 top
T2 "750343547" Wurth_750343473 3805,2291.5 r0 top
T3 "750343548" Wurth_750343473 3805,7678.01 r0 top
T4 "750340744" Wurth_750340744 1339.15,2819 r90 top
T5 "750340744" Wurth_750340744 1415,4614.89 r90 top
T6 "750340744" Wurth_750340744 1415,8205.9 r90 top
T7 "750343548" Wurth_750343473 3805,5882.5 r0 top
T8 "750340744" Wurth_750340744 1339.15,6410.01 r90 top
U1 "LM5030MM/NOPB" MUB10A_N 1429.13,4008 r90 top
U2 "TLV171IDBVR" DBV0005A_N 1749,3537 r90 top
U3 "TPS7A4901DGNR" DGN0008D_N 431.83,858.87 r0 top
U4 "LM5030MM/NOPB" MUB10A_N 1354.13,2216.43 r90 top
U5 "TLV2171IDR" D0008A_N 1774.46,1754 r90 top
U6 "TPS7A4901DGNR" DGN0008D_N 431.83,535 r0 top
U7 "LMZ34202RVQ" RVQ0043A 3342.11,673.73 r0 top locked
U8 "LMZ34202RVQ" RVQ0043A 4351.11,665 r0 top locked
U9 "LMZ34002RKGR" RKG0041A 5283.11,695 r0 top
U10 "TPS7A4901DGNR" DGN0008D_N 2703.8,763.22 r90 top
U11 "DAC60004IPW14" PW0014A_N 1733.33,604.63 r0 top
U12 "DAC60004IPW14" PW0014A_N 604.1,6354.71 r0 top
U13 "REF5050AID" D0008A_N 1239.37,424.63 r0 bottom
U14 "LM5030MM/NOPB" MUB10A_N 1429.13,7599.01 r90 top
U15 "TLV171IDBVR" DBV0005A_N 1750.12,7127.94 r90 top
U16 "CDCE937PWR" PW0020A_N 572.03,1304.06 r0 top
U17 "LM5030MM/NOPB" MUB10A_N 1354.13,5807.43 r90 top
U18 "TLV2171IDR" D0008A_N 1775.56,5340.7 r90 top
VCON-A1 "5002" Keystone5002 1377,919 r270 top
VCON-A2 "5002" Keystone5002 265,6710 r180 top
VCON-B1 "5002" Keystone5002 1997,758 r90 top
VCON-B2 "5002" Keystone5002 945,6590 r180 top
VCON-C1 "5002" Keystone5002 1577,919 r90 top
VCON-C2 "5002" Keystone5002 495,6710 r180 top
VCON-D1 "5002" Keystone5002 1792,919 r90 top
VCON-D2 "5002" Keystone5002 775,6710 r180 top
VDD_5V3 "5002" Keystone5002 2491.8,421.02 r90 top
VREF_5V "5002" Keystone5002 1463.26,303.63 r90 top
Y1 "406I35D08M00000" CTS_406 540,1535 r270 top
ZZ8 "This Assembly Note is for PCB labels only" AssemblyNoteLabel -453,6018 r0 top
ZZ9 "These assemblies are ESD sensitive, ESD precautions shall be observed." AssemblyNote -456.89,5947.55 r0 top
ZZ10 "These assemblies must be clean and free from flux and all contaminants. Use of no clean flux is not acceptable." AssemblyNote -452.89,5877.55 r0 top
ZZ11 "These assemblies must comply with workmanship standards IPC-A-610 Class 2, unless otherwise specified." AssemblyNote -444.89,5807.55 r0 top

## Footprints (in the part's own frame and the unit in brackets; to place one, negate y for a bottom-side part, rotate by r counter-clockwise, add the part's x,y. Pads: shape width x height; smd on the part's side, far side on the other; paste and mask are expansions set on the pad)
0603#1 [mm] "0603 from SM-752 data"
  rect 1x0.95 smd: 1(-0.8,0) 2(0.8,0)
  silkscreen extent -1.52,-0.69 1.52,0.69
0603#2 [mm] "0603 from SM-752 data"
  rect 1x0.95 smd: 1(-0.8,-1.611) 2(0.8,-1.611)
  silkscreen extent -1.52,-2.3 1.52,-0.92
0805_HV [mil] "0805 with 30mil clearance between pads"
  rect 50x63 smd: 1(-40,0) 2(40,0)
  silkscreen extent -74,-40 74,40
1206 [mm] "1206 from SM-752 data"
  rect 1.3x1.85 smd: 1(-1.45,0) 2(1.45,0)
  silkscreen extent -2.4,-1.21 2.4,1.21
1206_180 [mm] "1206_180"
  rect 1.1x1.6 smd: 1(-1.7,0) 2(1.7,0)
  silkscreen extent -0.9,-1 0.9,1
1210_270 [mm] "1210"
  rect 1.3x2.7 smd: 1(-1.45,0) 2(1.45,0)
  silkscreen extent -2.32,-1.57 2.32,1.57
1210_280 [mm] "SMD, 2-Leads, Body 3.6x2.8mm, Height 2.8mm"
  rect 1.1x2.2 smd: 1(-1.65,0) 2(1.65,0)
  silkscreen extent -0.84,-1.4 0.84,1.4
2220_200 [mm] "Chip Capacitor, Body 5.7x5.0mm, IPC Medium Density"
  rect 1.6x5.3 smd: 1(-2.6,0) 2(2.6,0)
  silkscreen extent -3.69,-2.94 3.69,2.94
5108 [mm] "Keystone"
  rect 1.01x1.73 smd: 1(-1.445,0) 2(1.445,0)
1447440C [mm] "TH, 2-Leads, Dia 29.8mm, Pin Spacing 29mm"
  round 2.5 hole 1.9: 1(-14.5,0) 2(14.5,0)
  silkscreen extent -15.7,-15.7 15.7,15.7
Aavid_577202B04000G [mm] "HEATSINK TO-220 .500\" COMPACT"
  round 2.25 hole 1.73: 1(0,0)
  silkscreen extent -6.6,0.41 6.6,13.11
ASMN_V6560X [mm] "TH, 2-Leads, Body 29x12mm, Pitch 25.4mm"
  round 3.05 hole 2.55: 1(-12.7,0) 2(12.7,0)
  silkscreen extent -15,-3 15,9
AssemblyNote [mil] "Assembly Note"
AssemblyNoteLabel [mil] "Assembly Note for PCB Labels"
CTS_406 [mm] "SMD, 4-Leads, Body 6.2x3.7mm"
  rect 1.4x1.9 smd: 1(-1.2,2.2) 2(-1.2,-2.2) 3(1.2,-2.2) 4(1.2,2.2)
  silkscreen extent -2.66,-3.1 1.85,3.1
D0008A_N [mm] "SOIC, 8-Leads, Body 4.9x3.9mm, Pitch 1.27mm, IPC Medium Density"
  oval 1.45x0.6 smd: 1(-2.725,1.905) 2(-2.725,0.635) 3(-2.725,-0.635) 4(-2.725,-1.905) 5(2.725,-1.905) 6(2.725,-0.635) 7(2.725,0.635) 8(2.725,1.905)
  silkscreen extent -3.3,-2.5 0.9,2.5
DBV0005A_N [mm] "SOT23, 5-Leads, Body 2.9x1.6mm, Pitch 0.95mm, Lead Span 2.8mm, IPC Medium Density"
  rrect17% 1x0.6 smd: 1(-1.375,0.95) 2(-1.375,0) 3(-1.375,-0.95) 4(1.375,-0.95) 5(1.375,0.95)
  silkscreen extent -1.63,-1.55 0.38,1.55
DGN0008D_N [mm] "TSOP, 8-Leads, Body 3x3mm, Pitch 0.65mm, Thermal Pad 1.89x1.57mm, IPC Medium Density"
  rrect100% 1.35x0.45 smd: 1(-2.225,0.975) 2(-2.225,0.325) 3(-2.225,-0.325) 4(-2.225,-0.975) 5(2.225,-0.975) 6(2.225,-0.325) 7(2.225,0.325) 8(2.225,0.975)
  rrect6% 1.57x1.89 smd: 9(0,0)
  silkscreen extent -2.73,-1.55 0.95,1.55
ESD_Overlay_medium [mil]
  silkscreen extent -127,-109 125,110
EURoHS_Exempt_60mil [mil] "EU RoHS Exempt symbol"
Fairchild_SOD-523F [mm] "SMD, 2-Leads, Body 1.2x0.8mm"
  rect 0.8x0.5 smd: 1(-1,0) 2(1,0)
  silkscreen extent -2.03,-0.65 1.4,0.65
FCC_disclaimer [mil]
Fiducial10-20 [mm]
  round 1 smd mask+0: 1(0,0)
  Top Layer keep-out circle w1.178: c0,0 r0.5
Fuse_0678L [mm] "SMD, 2-Leads, Body 9.8x3.05mm"
  rrect3% 3.81x4.06 smd: 1(-4.705,0) 2(4.705,0)
  silkscreen extent -2.4,-1.6 2.4,1.6
Fuse_SSQ [mm] "Bel Fuse"
  rect 2x3.18 smd: 1(-2.5,0) 2(2.5,0)
  silkscreen extent -1.27,-1.32 1.27,1.32
IEC_Caution_small [mil]
  silkscreen extent -107,-93 107,92
IEC_HighVoltage_medium [mil]
  silkscreen extent -217,-176 217,200
KCS0003B [mm] "Flange Mount, 3-Leads, Body 10.16x4.51mm, Pitch 2.54mm"
  rrect25% 1.6x1.6 hole 1: 1(0,2.54)
  round 1.6 hole 1: 2(0,0) 3(0,-2.54)
  silkscreen extent -1.71,-5.08 2.86,5.08
Keystone5002 [mil] "For Keystone 500x miniature loop terminals"
  round 80 hole 40: 1(0,0)
  silkscreen extent -58,-58 58,58
Keystone_1902E [mil] "Hex Standoff, 4-40 threaded, nylon"
  round 1 on Mech4: 0(0,0)
Label_650x200 [mil] "Thermal Transfer Label"
  round 1 on Mech14: 0(0,0)
  silkscreen extent -325,-100 325,100
MUB10A_N [mm] "TSSOP, 10-Leads, Body 3x3mm, Pitch 0.5mm, IPC Medium Density"
  oval 1.7x0.3 smd: 1(-2.05,1) 2(-2.05,0.5) 3(-2.05,0) 4(-2.05,-0.5) 5(-2.05,-1) 6(2.05,-1) 7(2.05,-0.5) 8(2.05,0) 9(2.05,0.5) 10(2.05,1)
  silkscreen extent -2.17,-1.6 0.8,1.82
